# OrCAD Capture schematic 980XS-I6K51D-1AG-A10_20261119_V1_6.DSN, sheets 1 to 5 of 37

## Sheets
1 P0083_S8_MIPI: size A2
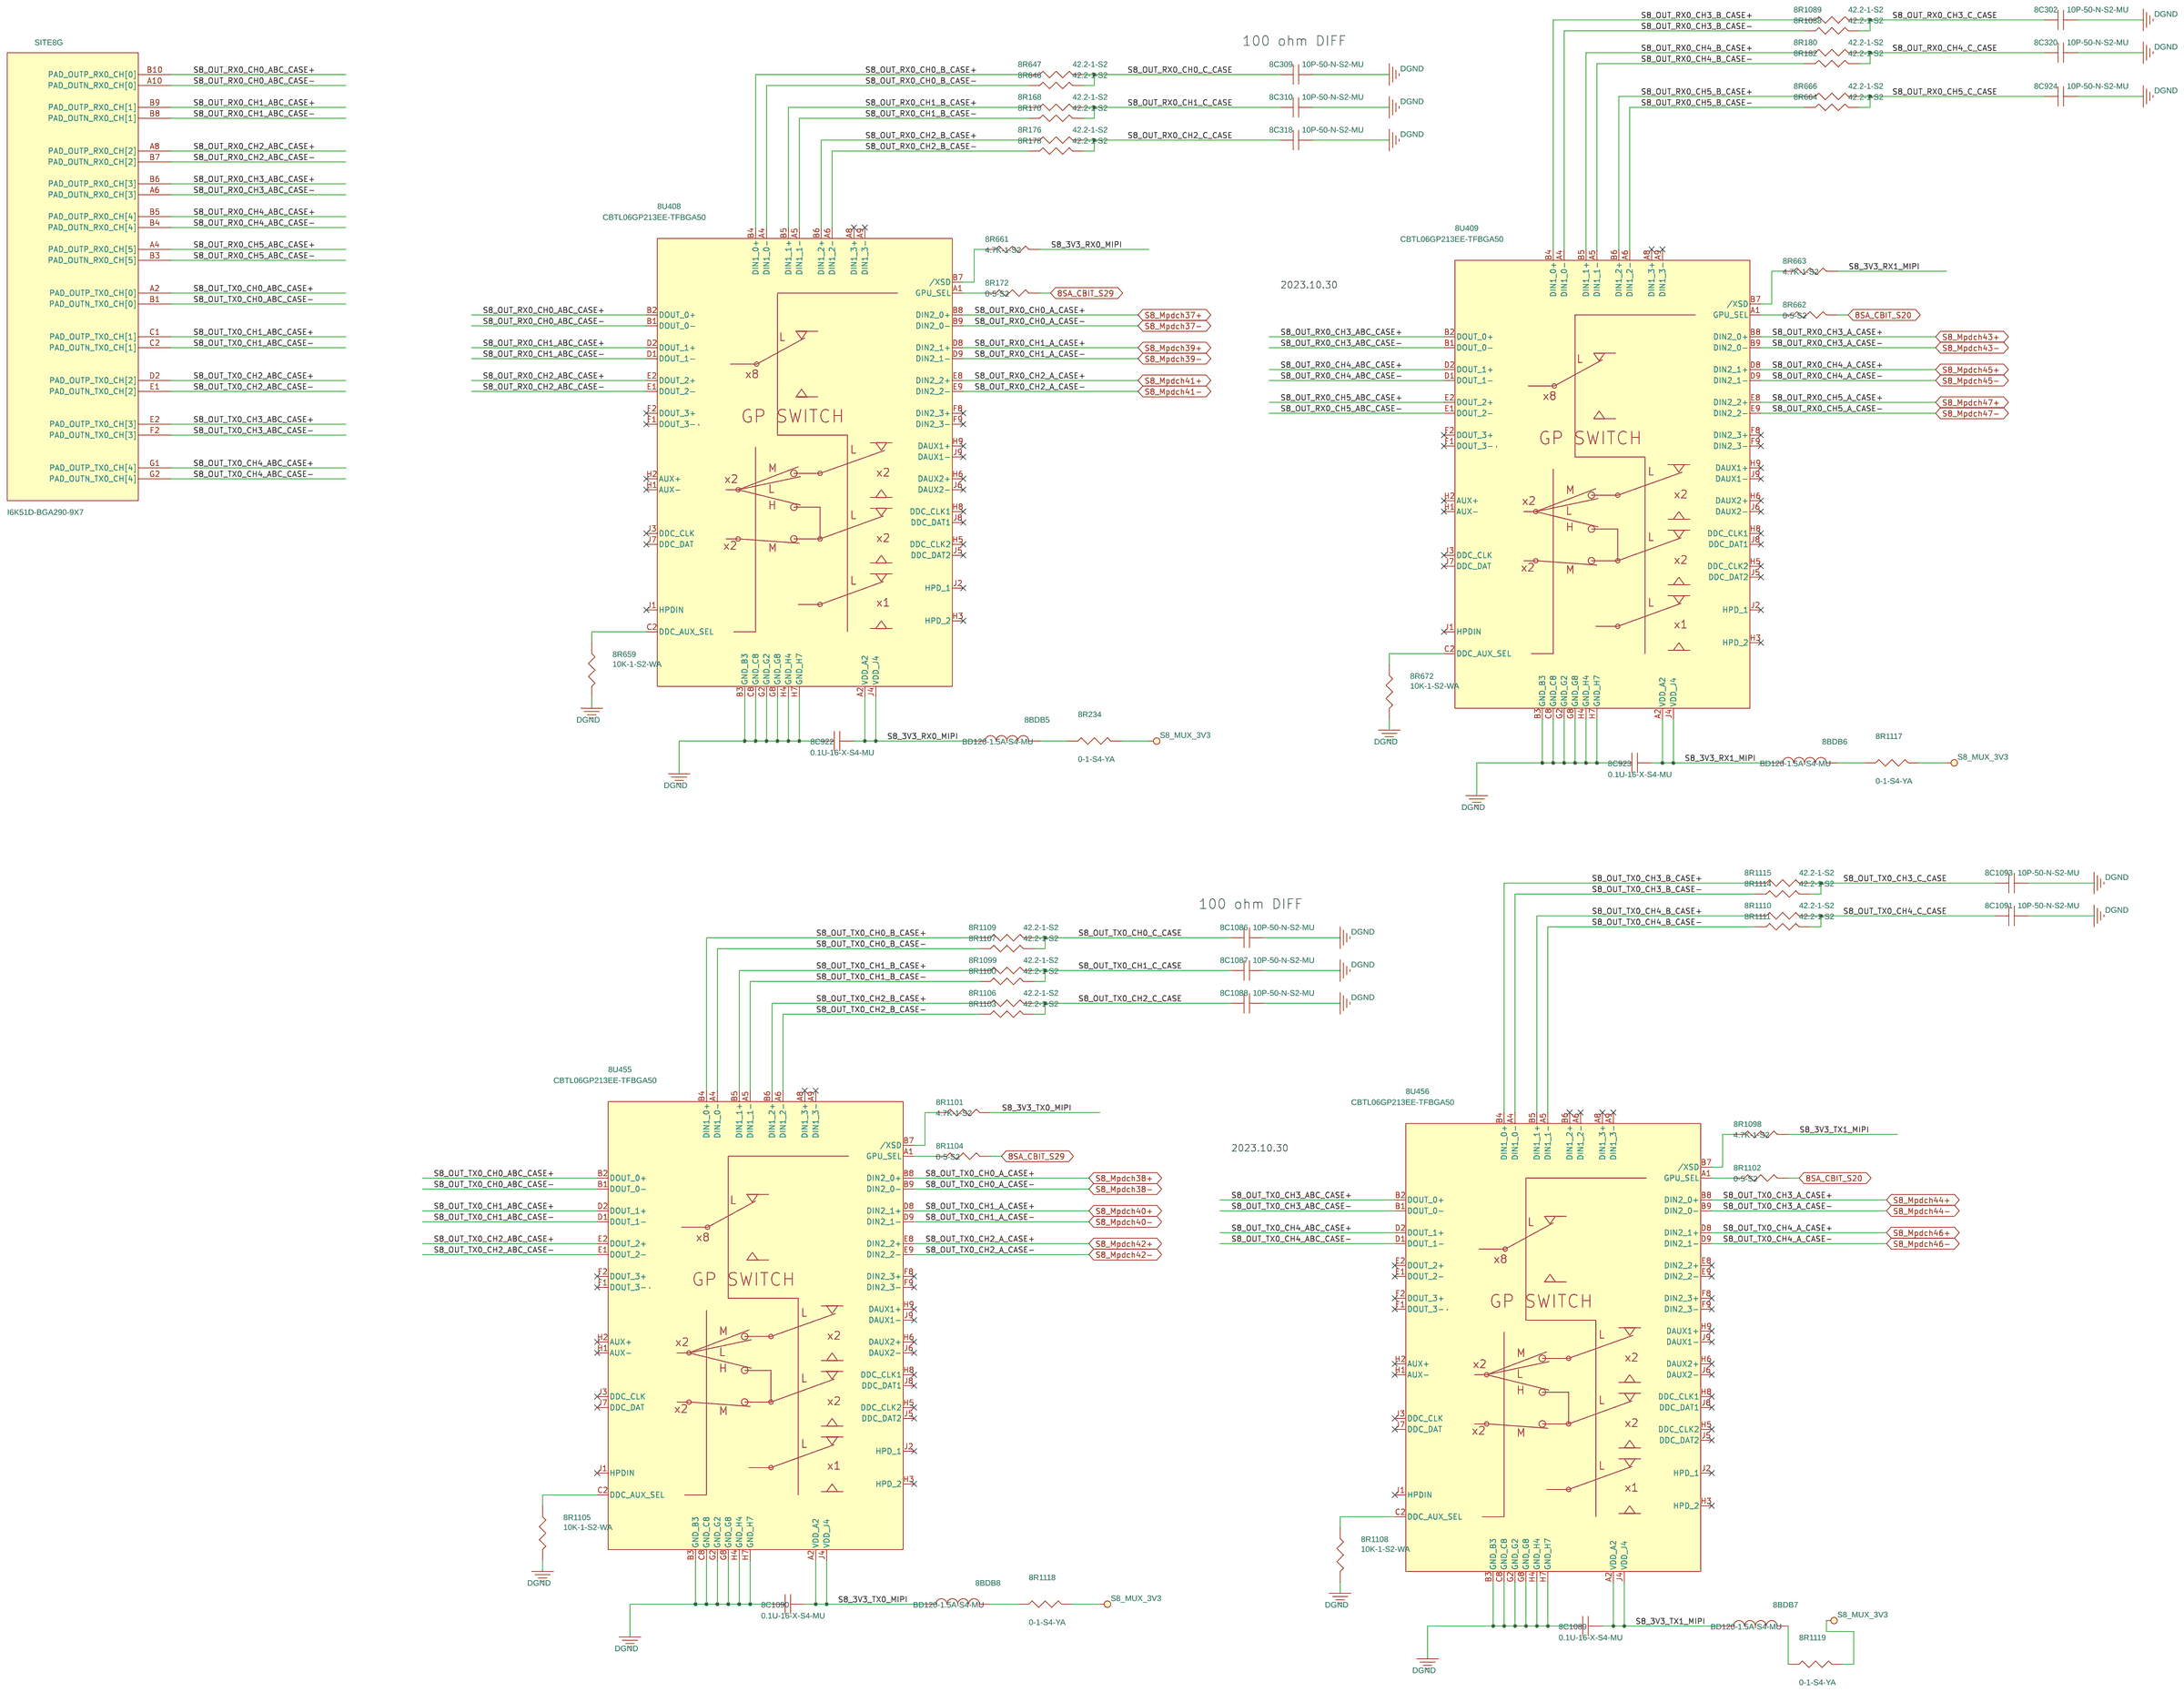
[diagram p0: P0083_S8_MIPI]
2 P0081_S8_POWER: size A2
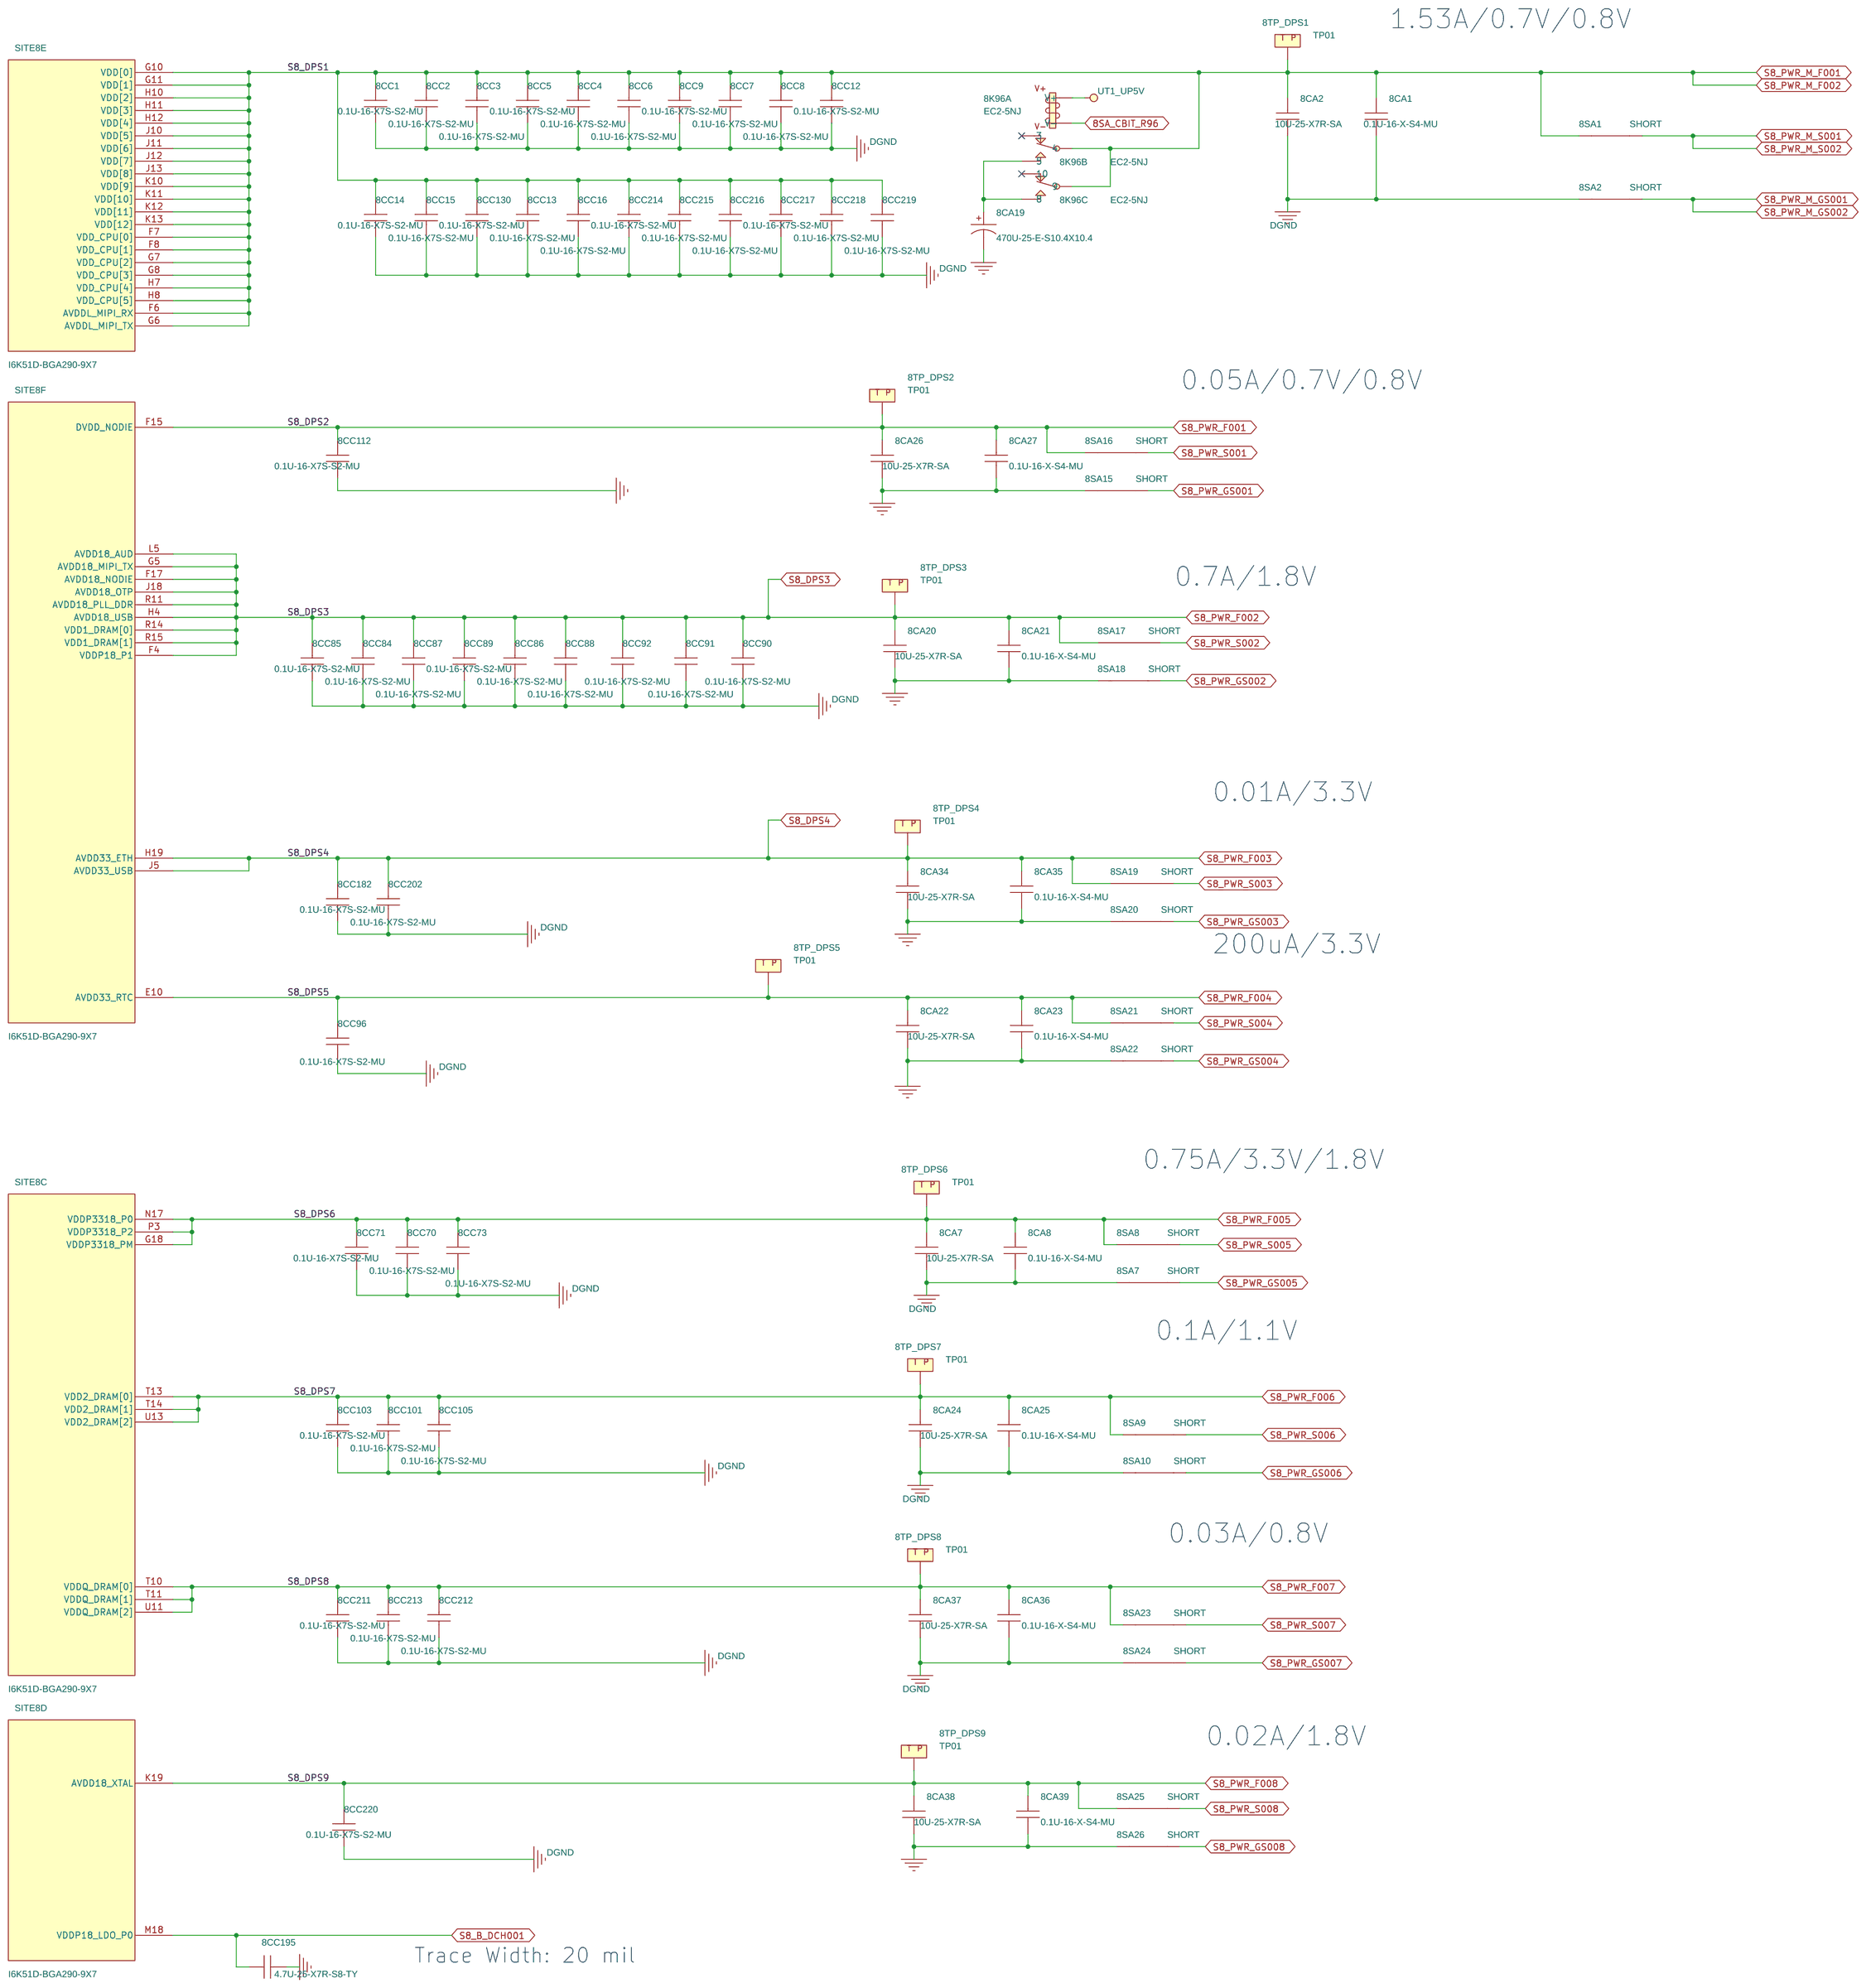
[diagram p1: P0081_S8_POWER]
3 P0073_S7_MIPI: size A2
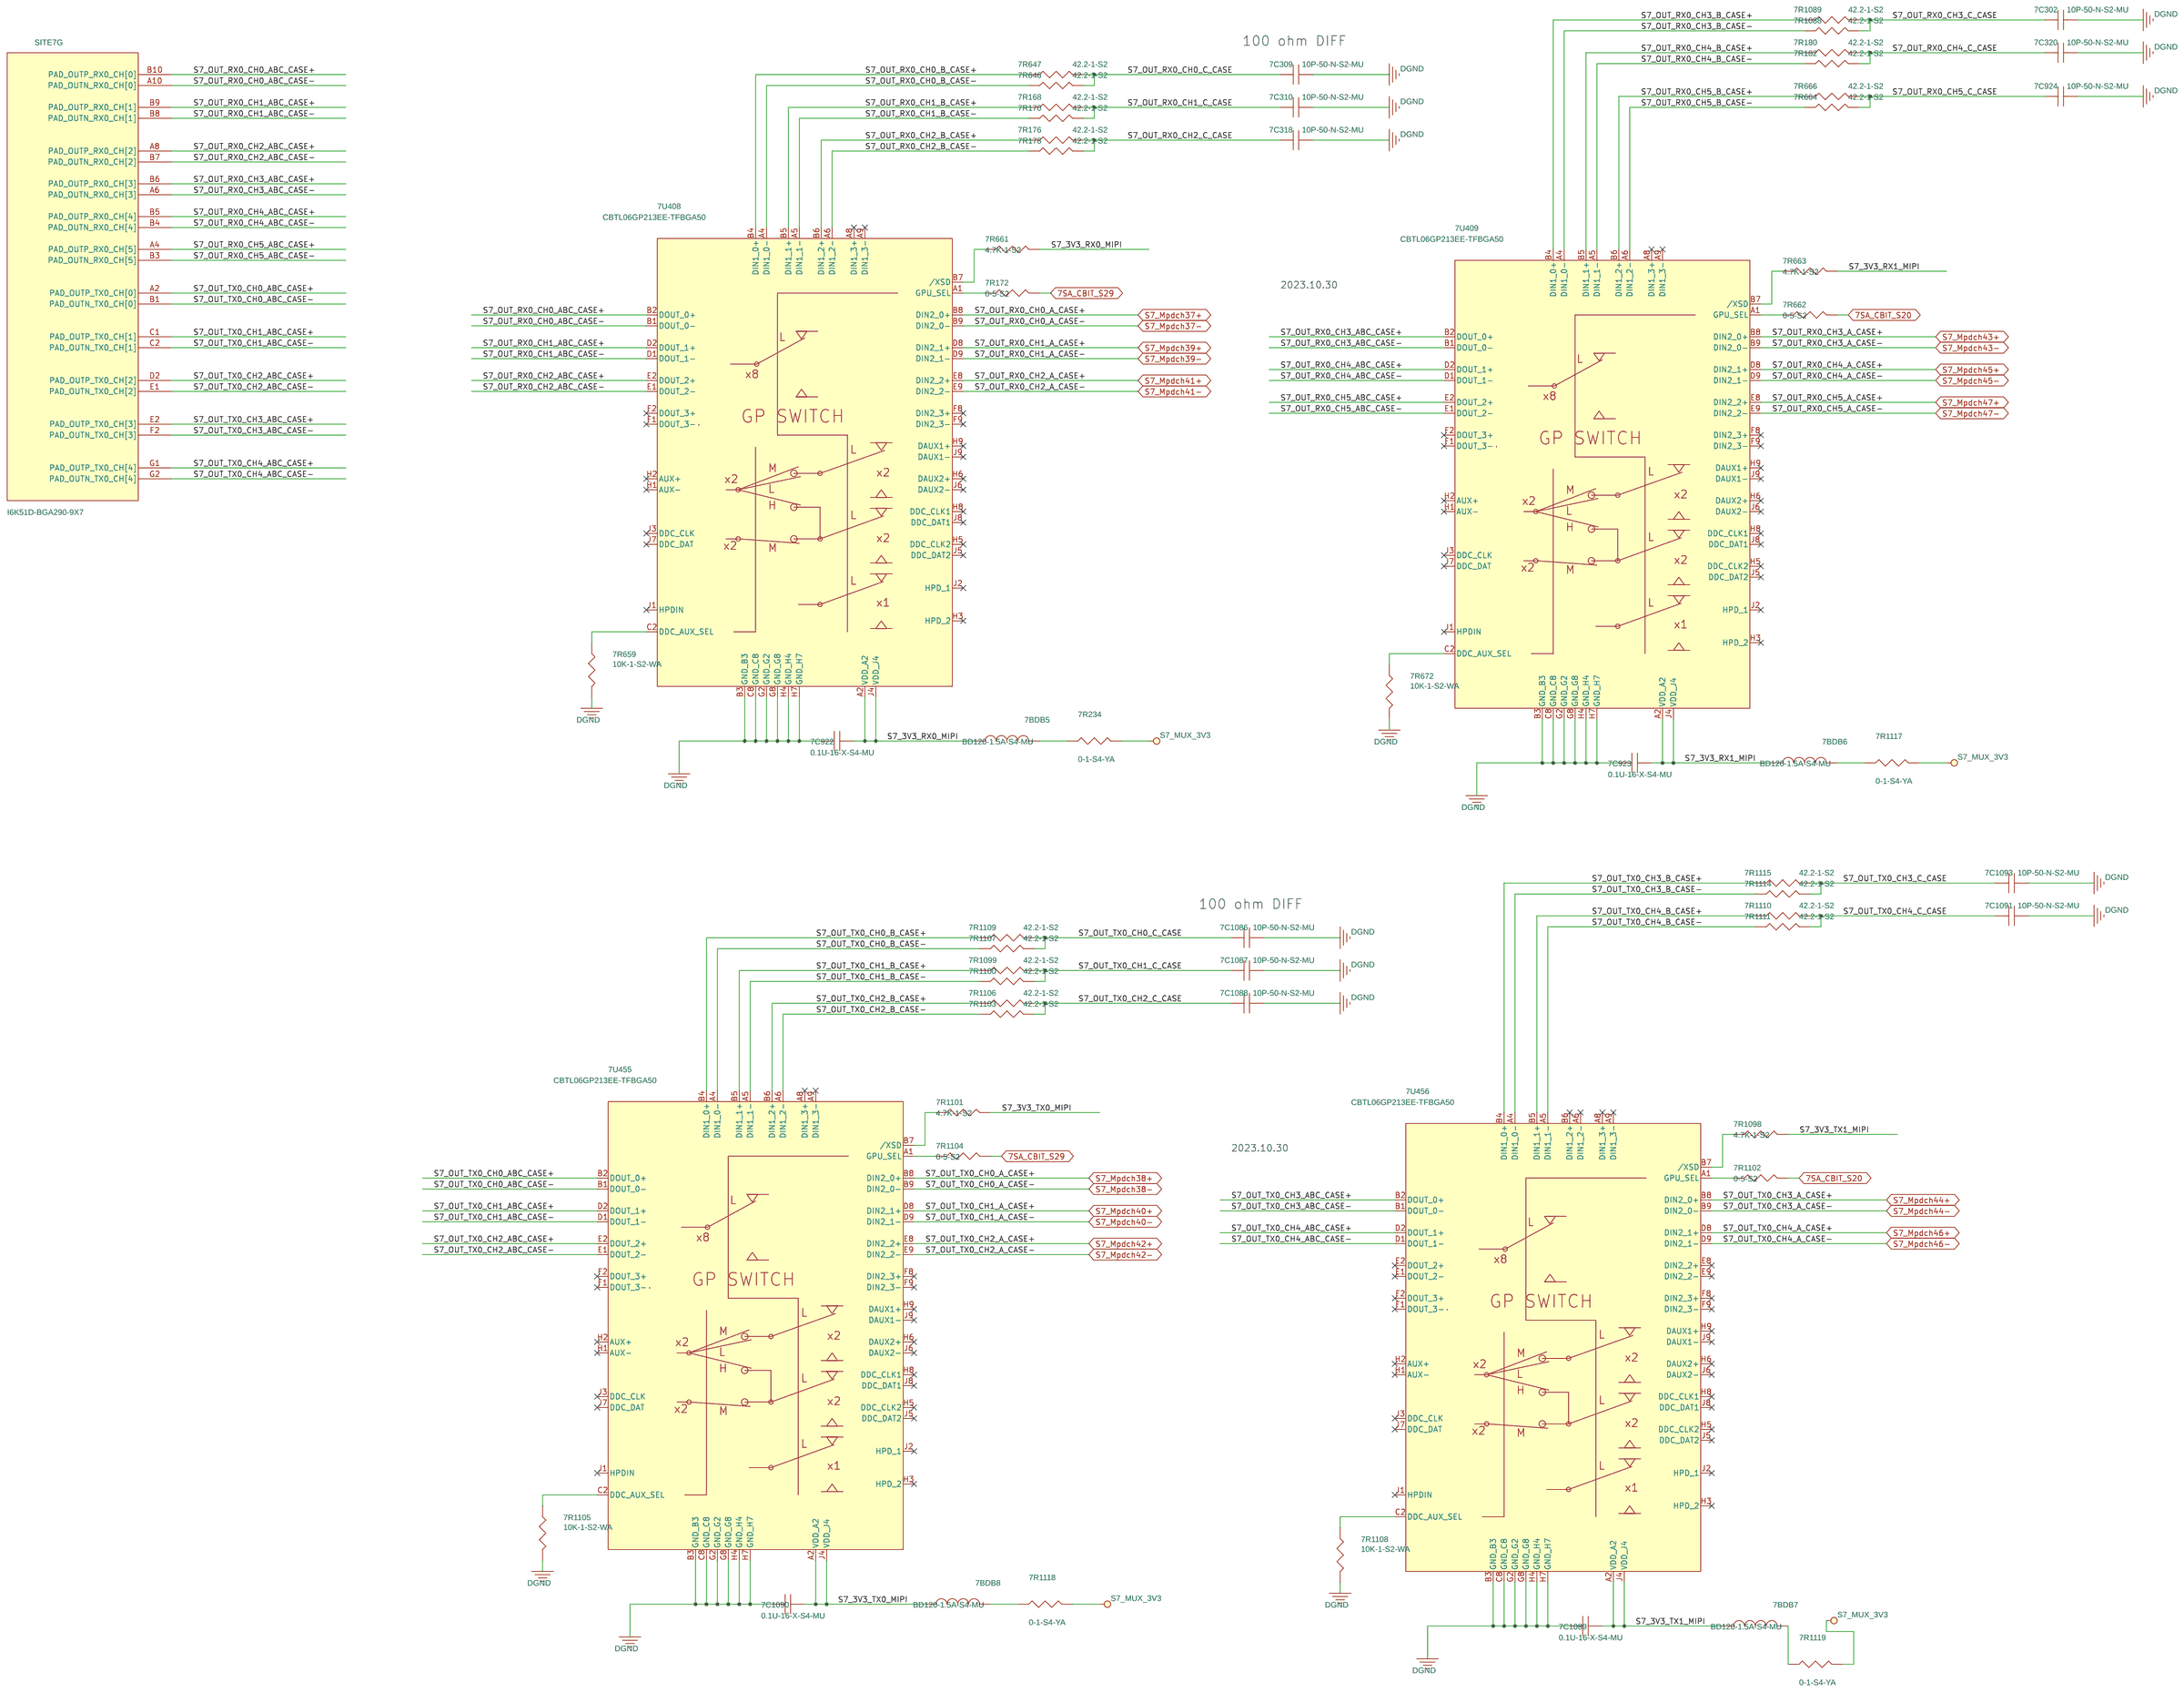
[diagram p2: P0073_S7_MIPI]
4 P0071_S7_POWER: size A2
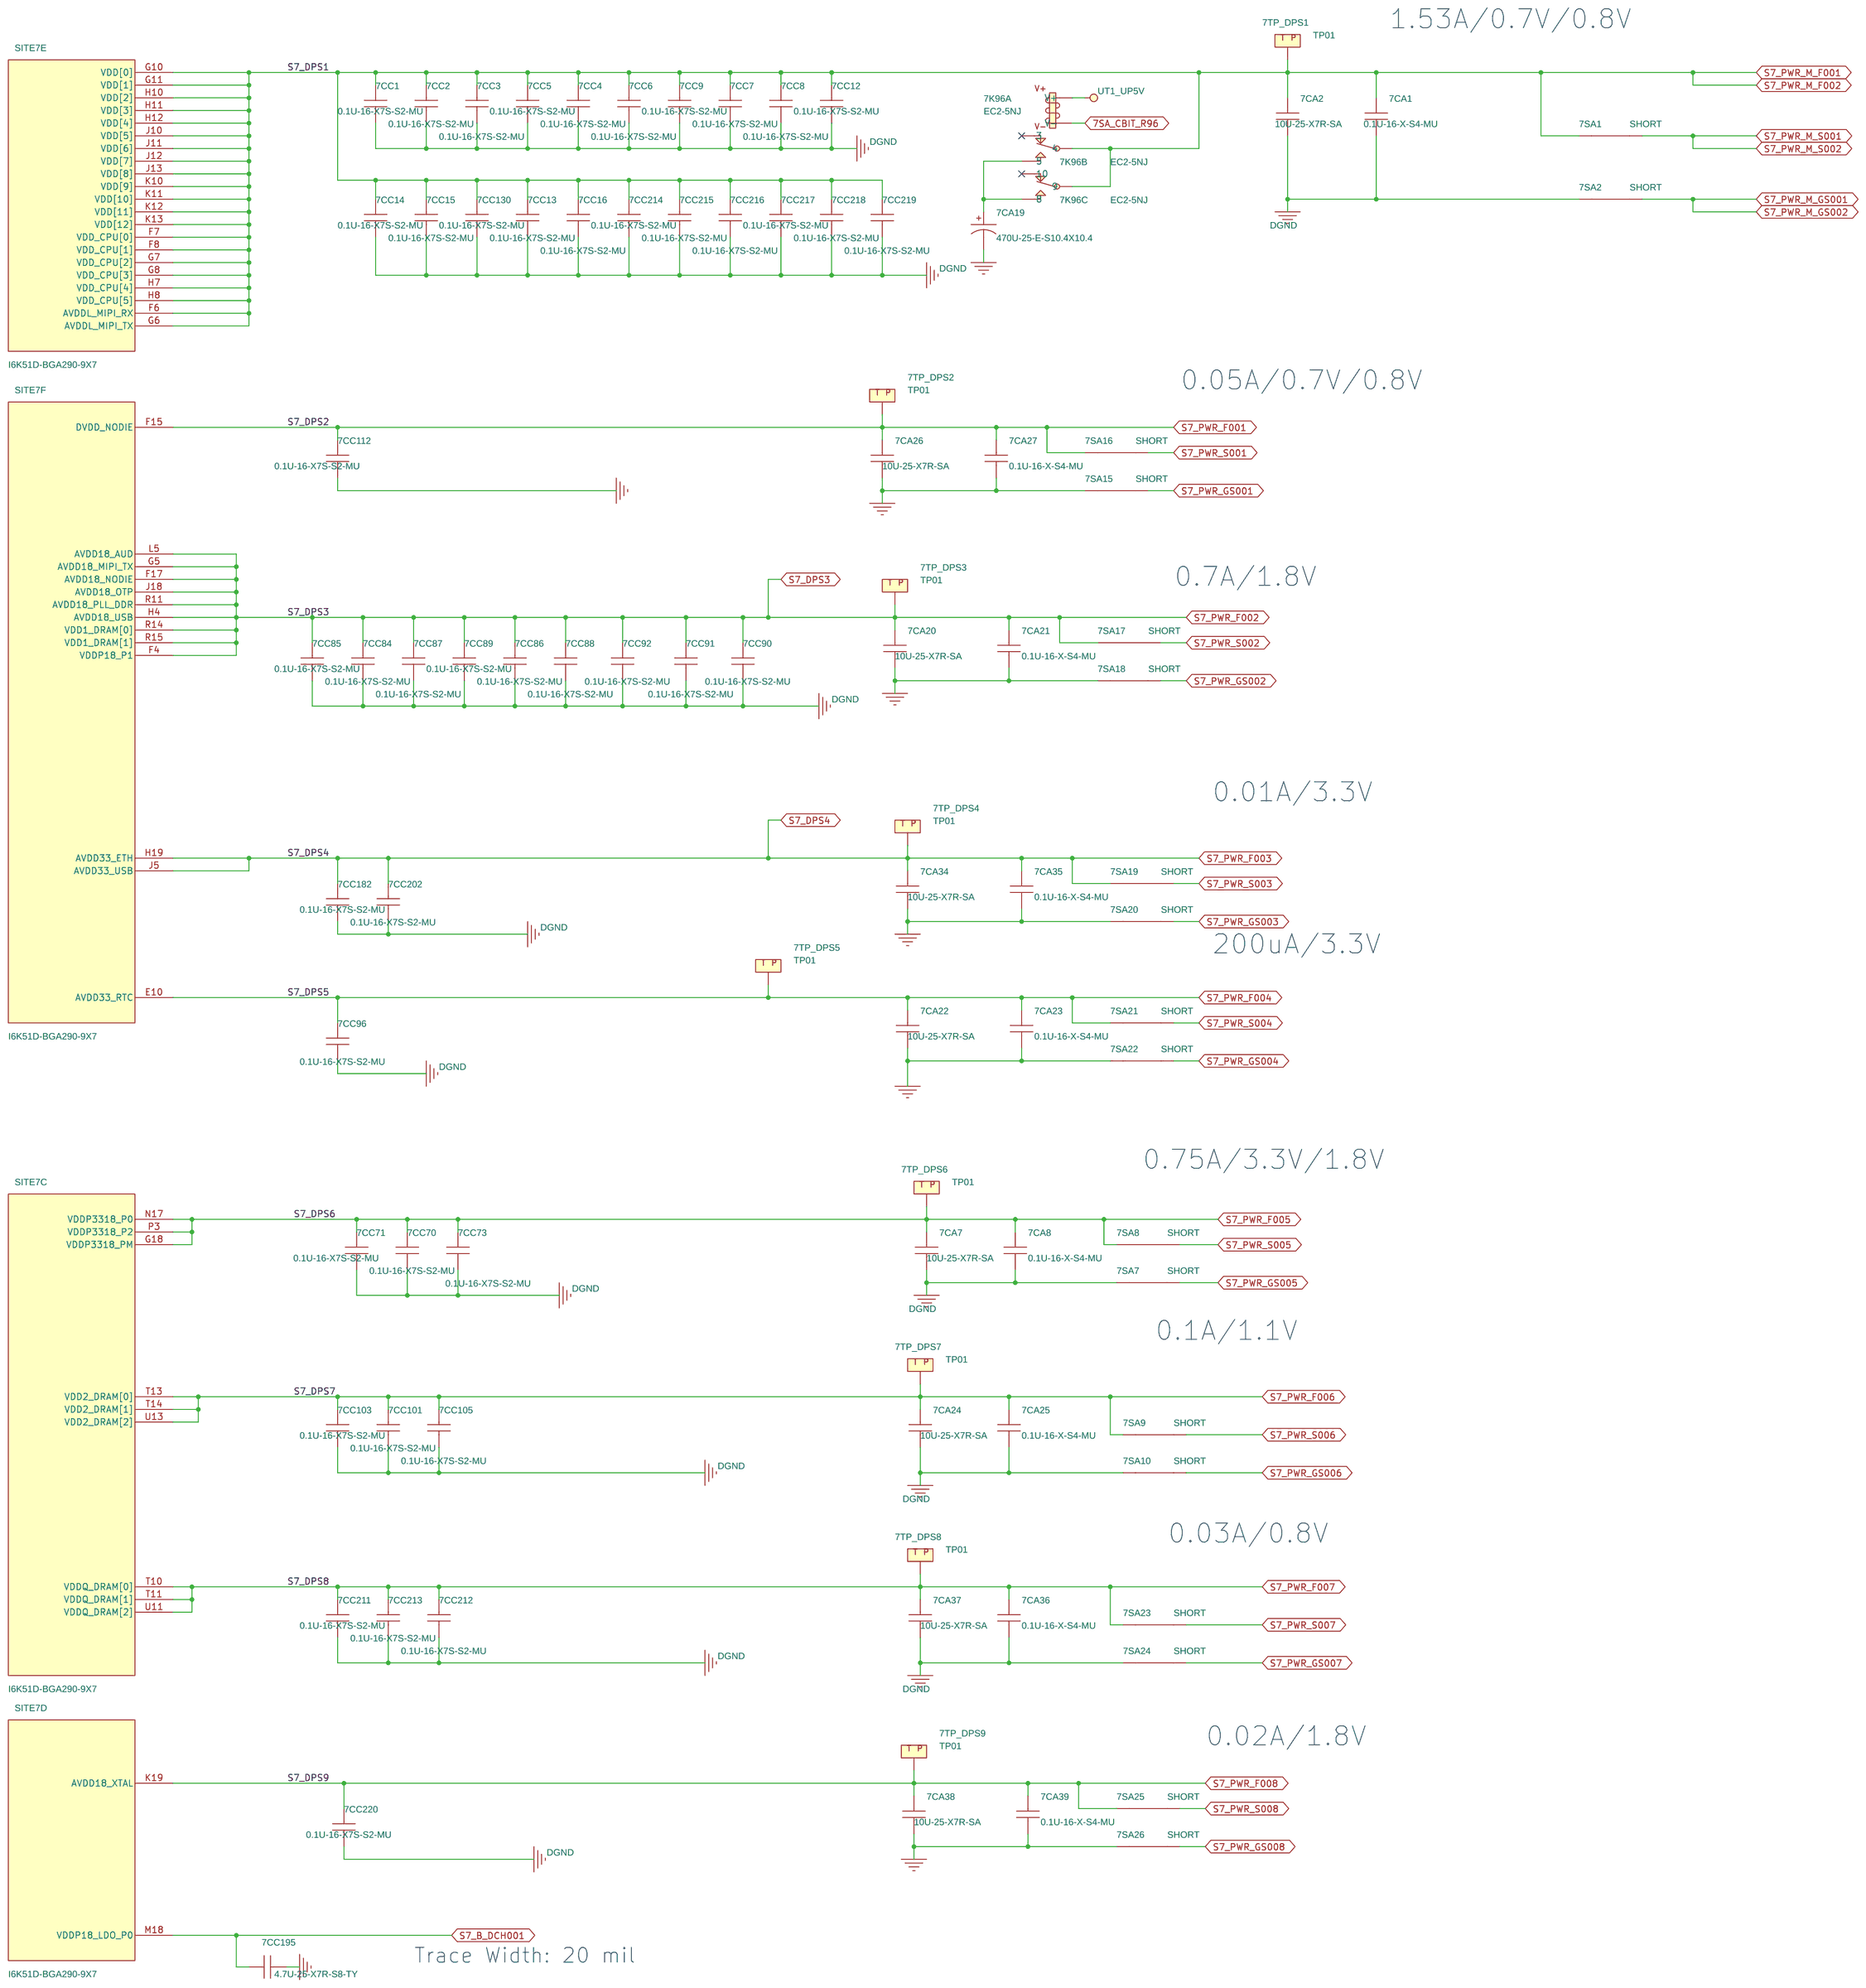
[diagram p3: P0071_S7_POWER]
5 P0063_S6_MIPI: size A2
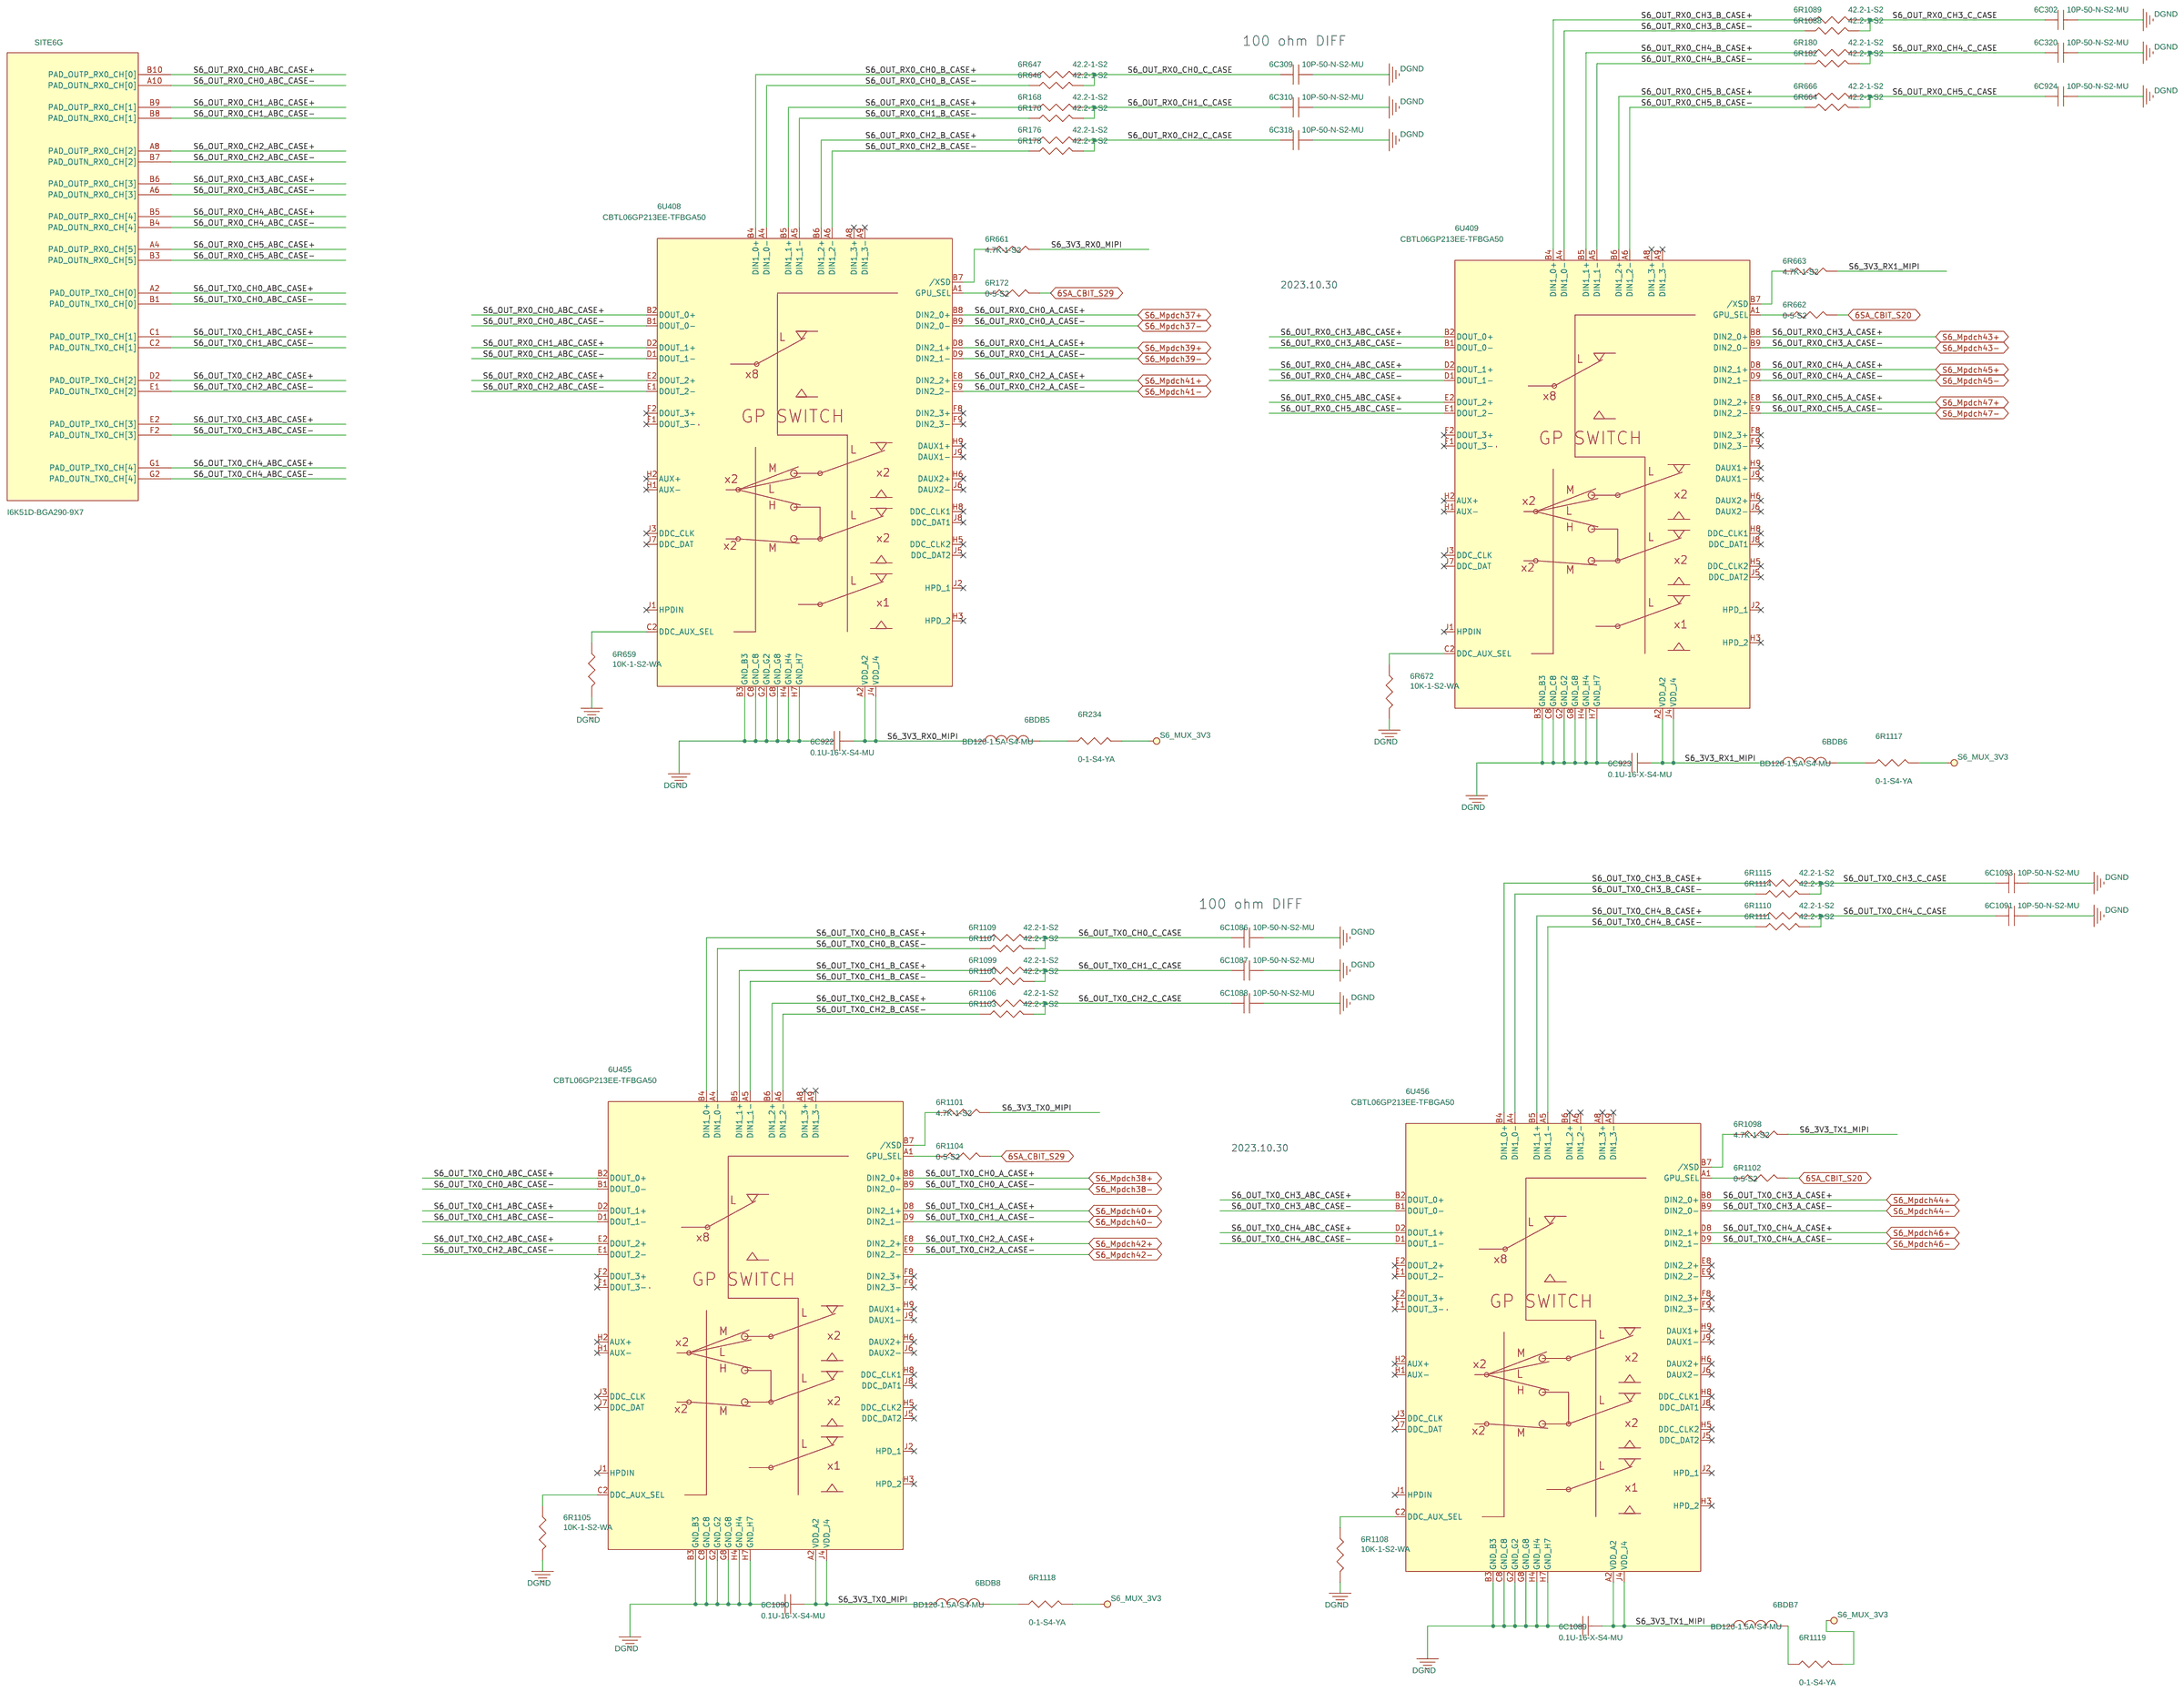
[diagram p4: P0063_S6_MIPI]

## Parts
sheet P0062_S6_USB/AUD/FLASH/XTAL
SITE6  I6K51D-BGA290-9X7  [SK_TFBGA7X9_290P_0P4MM_JG]  (sections A,B,C,D,E,F,G,H,I,J,K,L,M,N,O)
sheet P0063_S6_MIPI
6BDB5  BD120-1.5A-S4-MU  [FB0402]
6BDB6  BD120-1.5A-S4-MU  [FB0402]
6BDB7  BD120-1.5A-S4-MU  [FB0402]
6BDB8  BD120-1.5A-S4-MU  [FB0402]
6C302  10P-50-N-S2-MU  [C0201]
6C309  10P-50-N-S2-MU  [C0201]
6C310  10P-50-N-S2-MU  [C0201]
6C318  10P-50-N-S2-MU  [C0201]
6C320  10P-50-N-S2-MU  [C0201]
6C922  0.1U-16-X-S4-MU  [C0402]
6C923  0.1U-16-X-S4-MU  [C0402]
6C924  10P-50-N-S2-MU  [C0201]
6C1086  10P-50-N-S2-MU  [C0201]
6C1087  10P-50-N-S2-MU  [C0201]
6C1088  10P-50-N-S2-MU  [C0201]
6C1089  0.1U-16-X-S4-MU  [C0402]
6C1090  0.1U-16-X-S4-MU  [C0402]
6C1091  10P-50-N-S2-MU  [C0201]
6C1093  10P-50-N-S2-MU  [C0201]
6R168  42.2-1-S2  [R0201]
6R170  42.2-1-S2  [R0201]
6R172  0-5-S2  [R0201]
6R176  42.2-1-S2  [R0201]
6R178  42.2-1-S2  [R0201]
6R180  42.2-1-S2  [R0201]
6R182  42.2-1-S2  [R0201]
6R234  0-1-S4-YA  [R0402]
6R646  42.2-1-S2  [R0201]
6R647  42.2-1-S2  [R0201]
6R659  10K-1-S2-WA  [R0201]
6R661  4.7K-1-S2  [R0201]
6R662  0-5-S2  [R0201]
6R663  4.7K-1-S2  [R0201]
6R664  42.2-1-S2  [R0201]
6R666  42.2-1-S2  [R0201]
6R672  10K-1-S2-WA  [R0201]
6R1088  42.2-1-S2  [R0201]
6R1089  42.2-1-S2  [R0201]
6R1098  4.7K-1-S2  [R0201]
6R1099  42.2-1-S2  [R0201]
6R1100  42.2-1-S2  [R0201]
6R1101  4.7K-1-S2  [R0201]
6R1102  0-5-S2  [R0201]
6R1103  42.2-1-S2  [R0201]
6R1104  0-5-S2  [R0201]
6R1105  10K-1-S2-WA  [R0201]
6R1106  42.2-1-S2  [R0201]
6R1107  42.2-1-S2  [R0201]
6R1108  10K-1-S2-WA  [R0201]
6R1109  42.2-1-S2  [R0201]
6R1110  42.2-1-S2  [R0201]
6R1111  42.2-1-S2  [R0201]
6R1114  42.2-1-S2  [R0201]
6R1115  42.2-1-S2  [R0201]
6R1117  0-1-S4-YA  [R0402]
6R1118  0-1-S4-YA  [R0402]
6R1119  0-1-S4-YA  [R0402]
6U408  CBTL06GP213EE-TFBGA50  [TFBGA9X9_50P_0P5MM]
6U409  CBTL06GP213EE-TFBGA50  [TFBGA9X9_50P_0P5MM]
6U455  CBTL06GP213EE-TFBGA50  [TFBGA9X9_50P_0P5MM]
6U456  CBTL06GP213EE-TFBGA50  [TFBGA9X9_50P_0P5MM]
sheet P0071_S7_POWER
7CA1  0.1U-16-X-S4-MU  [C0402]
7CA2  10U-25-X7R-SA  [C1206]
7CA7  10U-25-X7R-SA  [C1206]
7CA8  0.1U-16-X-S4-MU  [C0402]
7CA19  470U-25-E-S10.4X10.4  [EC_10P3X10_S]
7CA20  10U-25-X7R-SA  [C1206]
7CA21  0.1U-16-X-S4-MU  [C0402]
7CA22  10U-25-X7R-SA  [C1206]
7CA23  0.1U-16-X-S4-MU  [C0402]
7CA24  10U-25-X7R-SA  [C1206]
7CA25  0.1U-16-X-S4-MU  [C0402]
7CA26  10U-25-X7R-SA  [C1206]
7CA27  0.1U-16-X-S4-MU  [C0402]
7CA34  10U-25-X7R-SA  [C1206]
7CA35  0.1U-16-X-S4-MU  [C0402]
7CA36  0.1U-16-X-S4-MU  [C0402]
7CA37  10U-25-X7R-SA  [C1206]
7CA38  10U-25-X7R-SA  [C1206]
7CA39  0.1U-16-X-S4-MU  [C0402]
7CC1  0.1U-16-X7S-S2-MU  [C0201_MINI]
7CC2  0.1U-16-X7S-S2-MU  [C0201_MINI]
7CC3  0.1U-16-X7S-S2-MU  [C0201_MINI]
7CC4  0.1U-16-X7S-S2-MU  [C0201_MINI]
7CC5  0.1U-16-X7S-S2-MU  [C0201_MINI]
7CC6  0.1U-16-X7S-S2-MU  [C0201_MINI]
7CC7  0.1U-16-X7S-S2-MU  [C0201_MINI]
7CC8  0.1U-16-X7S-S2-MU  [C0201_MINI]
7CC9  0.1U-16-X7S-S2-MU  [C0201_MINI]
7CC12  0.1U-16-X7S-S2-MU  [C0201_MINI]
7CC13  0.1U-16-X7S-S2-MU  [C0201_MINI]
7CC14  0.1U-16-X7S-S2-MU  [C0201_MINI]
7CC15  0.1U-16-X7S-S2-MU  [C0201_MINI]
7CC16  0.1U-16-X7S-S2-MU  [C0201_MINI]
7CC70  0.1U-16-X7S-S2-MU  [C0201_MINI]
7CC71  0.1U-16-X7S-S2-MU  [C0201_MINI]
7CC73  0.1U-16-X7S-S2-MU  [C0201_MINI]
7CC84  0.1U-16-X7S-S2-MU  [C0201_MINI]
7CC85  0.1U-16-X7S-S2-MU  [C0201_MINI]
7CC86  0.1U-16-X7S-S2-MU  [C0201_MINI]
7CC87  0.1U-16-X7S-S2-MU  [C0201_MINI]
7CC88  0.1U-16-X7S-S2-MU  [C0201_MINI]
7CC89  0.1U-16-X7S-S2-MU  [C0201_MINI]
7CC90  0.1U-16-X7S-S2-MU  [C0201_MINI]
7CC91  0.1U-16-X7S-S2-MU  [C0201_MINI]
7CC92  0.1U-16-X7S-S2-MU  [C0201_MINI]
7CC96  0.1U-16-X7S-S2-MU  [C0201_MINI]
7CC101  0.1U-16-X7S-S2-MU  [C0201_MINI]
7CC103  0.1U-16-X7S-S2-MU  [C0201_MINI]
7CC105  0.1U-16-X7S-S2-MU  [C0201_MINI]
7CC112  0.1U-16-X7S-S2-MU  [C0201_MINI]
7CC130  0.1U-16-X7S-S2-MU  [C0201_MINI]
7CC182  0.1U-16-X7S-S2-MU  [C0201_MINI]
7CC195  4.7U-25-X7R-S8-TY  [C0805]
7CC202  0.1U-16-X7S-S2-MU  [C0201_MINI]
7CC211  0.1U-16-X7S-S2-MU  [C0201_MINI]
7CC212  0.1U-16-X7S-S2-MU  [C0201_MINI]
7CC213  0.1U-16-X7S-S2-MU  [C0201_MINI]
7CC214  0.1U-16-X7S-S2-MU  [C0201_MINI]
7CC215  0.1U-16-X7S-S2-MU  [C0201_MINI]
7CC216  0.1U-16-X7S-S2-MU  [C0201_MINI]
7CC217  0.1U-16-X7S-S2-MU  [C0201_MINI]
7CC218  0.1U-16-X7S-S2-MU  [C0201_MINI]
7CC219  0.1U-16-X7S-S2-MU  [C0201_MINI]
7CC220  0.1U-16-X7S-S2-MU  [C0201_MINI]
7K96  EC2-5NJ  [RL_NECEC2_10P_5V]  (sections A,B,C)
7SA1  SHORT  [DEFAULT_SHORT_SMALL]
7SA2  SHORT  [DEFAULT_SHORT_SMALL]
7SA7  SHORT  [DEFAULT_SHORT_SMALL]
7SA8  SHORT  [DEFAULT_SHORT_SMALL]
7SA9  SHORT  [DEFAULT_SHORT_SMALL]
7SA10  SHORT  [DEFAULT_SHORT_SMALL]
7SA15  SHORT  [DEFAULT_SHORT_SMALL]
7SA16  SHORT  [DEFAULT_SHORT_SMALL]
7SA17  SHORT  [DEFAULT_SHORT_SMALL]
7SA18  SHORT  [DEFAULT_SHORT_SMALL]
7SA19  SHORT  [DEFAULT_SHORT_SMALL]
7SA20  SHORT  [DEFAULT_SHORT_SMALL]
7SA21  SHORT  [DEFAULT_SHORT_SMALL]
7SA22  SHORT  [DEFAULT_SHORT_SMALL]
7SA23  SHORT  [DEFAULT_SHORT_SMALL]
7SA24  SHORT  [DEFAULT_SHORT_SMALL]
7SA25  SHORT  [DEFAULT_SHORT_SMALL]
7SA26  SHORT  [DEFAULT_SHORT_SMALL]
7TP_DPS1  TP01  [TP_040_T]
7TP_DPS2  TP01  [TP_040_T]
7TP_DPS3  TP01  [TP_040_T]
7TP_DPS4  TP01  [TP_040_T]
7TP_DPS5  TP01  [TP_040_T]
7TP_DPS6  TP01  [TP_040_T]
7TP_DPS7  TP01  [TP_040_T]
7TP_DPS8  TP01  [TP_040_T]
7TP_DPS9  TP01  [TP_040_T]
sheet P0072_S7_USB/AUD/FLASH/XTAL
SITE7  I6K51D-BGA290-9X7  [SK_TFBGA7X9_290P_0P4MM_JG]  (sections A,B,C,D,E,F,G,H,I,J,K,L,M,N,O)
sheet P0073_S7_MIPI
7BDB5  BD120-1.5A-S4-MU  [FB0402]
7BDB6  BD120-1.5A-S4-MU  [FB0402]
7BDB7  BD120-1.5A-S4-MU  [FB0402]
7BDB8  BD120-1.5A-S4-MU  [FB0402]
7C302  10P-50-N-S2-MU  [C0201]
7C309  10P-50-N-S2-MU  [C0201]
7C310  10P-50-N-S2-MU  [C0201]
7C318  10P-50-N-S2-MU  [C0201]
7C320  10P-50-N-S2-MU  [C0201]
7C922  0.1U-16-X-S4-MU  [C0402]
7C923  0.1U-16-X-S4-MU  [C0402]
7C924  10P-50-N-S2-MU  [C0201]
7C1086  10P-50-N-S2-MU  [C0201]
7C1087  10P-50-N-S2-MU  [C0201]
7C1088  10P-50-N-S2-MU  [C0201]
7C1089  0.1U-16-X-S4-MU  [C0402]
7C1090  0.1U-16-X-S4-MU  [C0402]
7C1091  10P-50-N-S2-MU  [C0201]
7C1093  10P-50-N-S2-MU  [C0201]
7R168  42.2-1-S2  [R0201]
7R170  42.2-1-S2  [R0201]
7R172  0-5-S2  [R0201]
7R176  42.2-1-S2  [R0201]
7R178  42.2-1-S2  [R0201]
7R180  42.2-1-S2  [R0201]
7R182  42.2-1-S2  [R0201]
7R234  0-1-S4-YA  [R0402]
7R646  42.2-1-S2  [R0201]
7R647  42.2-1-S2  [R0201]
7R659  10K-1-S2-WA  [R0201]
7R661  4.7K-1-S2  [R0201]
7R662  0-5-S2  [R0201]
7R663  4.7K-1-S2  [R0201]
7R664  42.2-1-S2  [R0201]
7R666  42.2-1-S2  [R0201]
7R672  10K-1-S2-WA  [R0201]
7R1088  42.2-1-S2  [R0201]
7R1089  42.2-1-S2  [R0201]
7R1098  4.7K-1-S2  [R0201]
7R1099  42.2-1-S2  [R0201]
7R1100  42.2-1-S2  [R0201]
7R1101  4.7K-1-S2  [R0201]
7R1102  0-5-S2  [R0201]
7R1103  42.2-1-S2  [R0201]
7R1104  0-5-S2  [R0201]
7R1105  10K-1-S2-WA  [R0201]
7R1106  42.2-1-S2  [R0201]
7R1107  42.2-1-S2  [R0201]
7R1108  10K-1-S2-WA  [R0201]
7R1109  42.2-1-S2  [R0201]
7R1110  42.2-1-S2  [R0201]
7R1111  42.2-1-S2  [R0201]
7R1114  42.2-1-S2  [R0201]
7R1115  42.2-1-S2  [R0201]
7R1117  0-1-S4-YA  [R0402]
7R1118  0-1-S4-YA  [R0402]
7R1119  0-1-S4-YA  [R0402]
7U408  CBTL06GP213EE-TFBGA50  [TFBGA9X9_50P_0P5MM]
7U409  CBTL06GP213EE-TFBGA50  [TFBGA9X9_50P_0P5MM]
7U455  CBTL06GP213EE-TFBGA50  [TFBGA9X9_50P_0P5MM]
7U456  CBTL06GP213EE-TFBGA50  [TFBGA9X9_50P_0P5MM]
sheet P0081_S8_POWER
8CA1  0.1U-16-X-S4-MU  [C0402]
8CA2  10U-25-X7R-SA  [C1206]
8CA7  10U-25-X7R-SA  [C1206]
8CA8  0.1U-16-X-S4-MU  [C0402]
8CA19  470U-25-E-S10.4X10.4  [EC_10P3X10_S]
8CA20  10U-25-X7R-SA  [C1206]
8CA21  0.1U-16-X-S4-MU  [C0402]
8CA22  10U-25-X7R-SA  [C1206]
8CA23  0.1U-16-X-S4-MU  [C0402]
8CA24  10U-25-X7R-SA  [C1206]
8CA25  0.1U-16-X-S4-MU  [C0402]
8CA26  10U-25-X7R-SA  [C1206]
8CA27  0.1U-16-X-S4-MU  [C0402]
8CA34  10U-25-X7R-SA  [C1206]
8CA35  0.1U-16-X-S4-MU  [C0402]
8CA36  0.1U-16-X-S4-MU  [C0402]
8CA37  10U-25-X7R-SA  [C1206]
8CA38  10U-25-X7R-SA  [C1206]
8CA39  0.1U-16-X-S4-MU  [C0402]
8CC1  0.1U-16-X7S-S2-MU  [C0201_MINI]
8CC2  0.1U-16-X7S-S2-MU  [C0201_MINI]
8CC3  0.1U-16-X7S-S2-MU  [C0201_MINI]
8CC4  0.1U-16-X7S-S2-MU  [C0201_MINI]
8CC5  0.1U-16-X7S-S2-MU  [C0201_MINI]
8CC6  0.1U-16-X7S-S2-MU  [C0201_MINI]
8CC7  0.1U-16-X7S-S2-MU  [C0201_MINI]
8CC8  0.1U-16-X7S-S2-MU  [C0201_MINI]
8CC9  0.1U-16-X7S-S2-MU  [C0201_MINI]
8CC12  0.1U-16-X7S-S2-MU  [C0201_MINI]
8CC13  0.1U-16-X7S-S2-MU  [C0201_MINI]
8CC14  0.1U-16-X7S-S2-MU  [C0201_MINI]
8CC15  0.1U-16-X7S-S2-MU  [C0201_MINI]
8CC16  0.1U-16-X7S-S2-MU  [C0201_MINI]
8CC70  0.1U-16-X7S-S2-MU  [C0201_MINI]
8CC71  0.1U-16-X7S-S2-MU  [C0201_MINI]
8CC73  0.1U-16-X7S-S2-MU  [C0201_MINI]
8CC84  0.1U-16-X7S-S2-MU  [C0201_MINI]
8CC85  0.1U-16-X7S-S2-MU  [C0201_MINI]
8CC86  0.1U-16-X7S-S2-MU  [C0201_MINI]
8CC87  0.1U-16-X7S-S2-MU  [C0201_MINI]
8CC88  0.1U-16-X7S-S2-MU  [C0201_MINI]
8CC89  0.1U-16-X7S-S2-MU  [C0201_MINI]
8CC90  0.1U-16-X7S-S2-MU  [C0201_MINI]
8CC91  0.1U-16-X7S-S2-MU  [C0201_MINI]
8CC92  0.1U-16-X7S-S2-MU  [C0201_MINI]
8CC96  0.1U-16-X7S-S2-MU  [C0201_MINI]
8CC101  0.1U-16-X7S-S2-MU  [C0201_MINI]
8CC103  0.1U-16-X7S-S2-MU  [C0201_MINI]
8CC105  0.1U-16-X7S-S2-MU  [C0201_MINI]
8CC112  0.1U-16-X7S-S2-MU  [C0201_MINI]
8CC130  0.1U-16-X7S-S2-MU  [C0201_MINI]
8CC182  0.1U-16-X7S-S2-MU  [C0201_MINI]
8CC195  4.7U-25-X7R-S8-TY  [C0805]
8CC202  0.1U-16-X7S-S2-MU  [C0201_MINI]
8CC211  0.1U-16-X7S-S2-MU  [C0201_MINI]
8CC212  0.1U-16-X7S-S2-MU  [C0201_MINI]
8CC213  0.1U-16-X7S-S2-MU  [C0201_MINI]
8CC214  0.1U-16-X7S-S2-MU  [C0201_MINI]
8CC215  0.1U-16-X7S-S2-MU  [C0201_MINI]
8CC216  0.1U-16-X7S-S2-MU  [C0201_MINI]
8CC217  0.1U-16-X7S-S2-MU  [C0201_MINI]
8CC218  0.1U-16-X7S-S2-MU  [C0201_MINI]
8CC219  0.1U-16-X7S-S2-MU  [C0201_MINI]
8CC220  0.1U-16-X7S-S2-MU  [C0201_MINI]
8K96  EC2-5NJ  [RL_NECEC2_10P_5V]  (sections A,B,C)
8SA1  SHORT  [DEFAULT_SHORT_SMALL]
8SA2  SHORT  [DEFAULT_SHORT_SMALL]
8SA7  SHORT  [DEFAULT_SHORT_SMALL]
8SA8  SHORT  [DEFAULT_SHORT_SMALL]
8SA9  SHORT  [DEFAULT_SHORT_SMALL]
8SA10  SHORT  [DEFAULT_SHORT_SMALL]
8SA15  SHORT  [DEFAULT_SHORT_SMALL]
8SA16  SHORT  [DEFAULT_SHORT_SMALL]
8SA17  SHORT  [DEFAULT_SHORT_SMALL]
8SA18  SHORT  [DEFAULT_SHORT_SMALL]
8SA19  SHORT  [DEFAULT_SHORT_SMALL]
8SA20  SHORT  [DEFAULT_SHORT_SMALL]
8SA21  SHORT  [DEFAULT_SHORT_SMALL]
8SA22  SHORT  [DEFAULT_SHORT_SMALL]
8SA23  SHORT  [DEFAULT_SHORT_SMALL]
8SA24  SHORT  [DEFAULT_SHORT_SMALL]
8SA25  SHORT  [DEFAULT_SHORT_SMALL]
8SA26  SHORT  [DEFAULT_SHORT_SMALL]
8TP_DPS1  TP01  [TP_040_T]
8TP_DPS2  TP01  [TP_040_T]
8TP_DPS3  TP01  [TP_040_T]
8TP_DPS4  TP01  [TP_040_T]
8TP_DPS5  TP01  [TP_040_T]
8TP_DPS6  TP01  [TP_040_T]
8TP_DPS7  TP01  [TP_040_T]
8TP_DPS8  TP01  [TP_040_T]
8TP_DPS9  TP01  [TP_040_T]
sheet P0083_S8_MIPI
8BDB5  BD120-1.5A-S4-MU  [FB0402]
8BDB6  BD120-1.5A-S4-MU  [FB0402]
8BDB7  BD120-1.5A-S4-MU  [FB0402]
8BDB8  BD120-1.5A-S4-MU  [FB0402]
8C302  10P-50-N-S2-MU  [C0201]
8C309  10P-50-N-S2-MU  [C0201]
8C310  10P-50-N-S2-MU  [C0201]
8C318  10P-50-N-S2-MU  [C0201]
8C320  10P-50-N-S2-MU  [C0201]
8C922  0.1U-16-X-S4-MU  [C0402]
8C923  0.1U-16-X-S4-MU  [C0402]
8C924  10P-50-N-S2-MU  [C0201]
8C1086  10P-50-N-S2-MU  [C0201]
8C1087  10P-50-N-S2-MU  [C0201]
8C1088  10P-50-N-S2-MU  [C0201]
8C1089  0.1U-16-X-S4-MU  [C0402]
8C1090  0.1U-16-X-S4-MU  [C0402]
8C1091  10P-50-N-S2-MU  [C0201]
8C1093  10P-50-N-S2-MU  [C0201]
8R168  42.2-1-S2  [R0201]
8R170  42.2-1-S2  [R0201]
8R172  0-5-S2  [R0201]
8R176  42.2-1-S2  [R0201]
8R178  42.2-1-S2  [R0201]
8R180  42.2-1-S2  [R0201]
8R182  42.2-1-S2  [R0201]
8R234  0-1-S4-YA  [R0402]
8R646  42.2-1-S2  [R0201]
8R647  42.2-1-S2  [R0201]
8R659  10K-1-S2-WA  [R0201]
8R661  4.7K-1-S2  [R0201]
8R662  0-5-S2  [R0201]
8R663  4.7K-1-S2  [R0201]
8R664  42.2-1-S2  [R0201]
8R666  42.2-1-S2  [R0201]
8R672  10K-1-S2-WA  [R0201]
8R1088  42.2-1-S2  [R0201]
8R1089  42.2-1-S2  [R0201]
8R1098  4.7K-1-S2  [R0201]
8R1099  42.2-1-S2  [R0201]
8R1100  42.2-1-S2  [R0201]
8R1101  4.7K-1-S2  [R0201]
8R1102  0-5-S2  [R0201]
8R1103  42.2-1-S2  [R0201]
8R1104  0-5-S2  [R0201]
8R1105  10K-1-S2-WA  [R0201]
8R1106  42.2-1-S2  [R0201]
8R1107  42.2-1-S2  [R0201]
8R1108  10K-1-S2-WA  [R0201]
8R1109  42.2-1-S2  [R0201]
8R1110  42.2-1-S2  [R0201]
8R1111  42.2-1-S2  [R0201]
8R1114  42.2-1-S2  [R0201]
8R1115  42.2-1-S2  [R0201]
8R1117  0-1-S4-YA  [R0402]
8R1118  0-1-S4-YA  [R0402]
8R1119  0-1-S4-YA  [R0402]
8U408  CBTL06GP213EE-TFBGA50  [TFBGA9X9_50P_0P5MM]
8U409  CBTL06GP213EE-TFBGA50  [TFBGA9X9_50P_0P5MM]
8U455  CBTL06GP213EE-TFBGA50  [TFBGA9X9_50P_0P5MM]
8U456  CBTL06GP213EE-TFBGA50  [TFBGA9X9_50P_0P5MM]
SITE8  I6K51D-BGA290-9X7  [SK_TFBGA7X9_290P_0P4MM_JG]  (sections A,B,C,D,E,F,G,H,I,J,K,L,M,N,O)

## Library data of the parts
SITE6-SITE8 = I6K51D-BGA290-9X7
6BDB5 6BDB8 7BDB5 7BDB8 8BDB5 8BDB8 = BD120-1.5A-S4-MU: KAIROSNAME: BDB5
6BDB6 6BDB7 7BDB6 7BDB7 8BDB6 8BDB7 = BD120-1.5A-S4-MU: KAIROSNAME: BDB6
6C302 6C318 6C1088 6C1093 7C302 7C318 7C1088 7C1093 8C302 8C318 8C1088 8C1093 = 10P-50-N-S2-MU: KAIROSNAME: C318
6C309 6C1086 7C309 7C1086 8C309 8C1086 = 10P-50-N-S2-MU: KAIROSNAME: C309
6C310 6C1087 7C310 7C1087 8C310 8C1087 = 10P-50-N-S2-MU: KAIROSNAME: C310
6C320 6C1091 7C320 7C1091 8C320 8C1091 = 10P-50-N-S2-MU: KAIROSNAME: C320
6C922 6C1090 7C922 7C1090 8C922 8C1090 = 0.1U-16-X-S4-MU: KAIROSNAME: C922
6C923 6C1089 7C923 7C1089 8C923 8C1089 = 0.1U-16-X-S4-MU: KAIROSNAME: C923
6C924 7C924 8C924 = 10P-50-N-S2-MU: KAIROSNAME: C924
6R168 6R1099 7R168 7R1099 8R168 8R1099 = 42.2-1-S2: KAIROSNAME: R168
6R170 6R1100 7R170 7R1100 8R170 8R1100 = 42.2-1-S2: KAIROSNAME: R170
6R172 6R1104 7R172 7R1104 8R172 8R1104 = 0-5-S2: KAIROSNAME: R172
6R176 6R1089 6R1106 6R1115 7R176 7R1089 7R1106 7R1115 8R176 8R1089 8R1106 8R1115 = 42.2-1-S2: KAIROSNAME: R176
6R178 6R1088 6R1103 6R1114 7R178 7R1088 7R1103 7R1114 8R178 8R1088 8R1103 8R1114 = 42.2-1-S2: KAIROSNAME: R178
6R180 6R1110 7R180 7R1110 8R180 8R1110 = 42.2-1-S2: KAIROSNAME: R180
6R182 6R1111 7R182 7R1111 8R182 8R1111 = 42.2-1-S2: KAIROSNAME: R182
6R234 6R1117-6R1119 7R234 7R1117-7R1119 8R234 8R1117-8R1119 = 0-1-S4-YA
6R646 6R1107 7R646 7R1107 8R646 8R1107 = 42.2-1-S2: KAIROSNAME: R646
6R647 6R1109 7R647 7R1109 8R647 8R1109 = 42.2-1-S2: KAIROSNAME: R647
6R659 6R1105 7R659 7R1105 8R659 8R1105 = 10K-1-S2-WA: KAIROSNAME: R659
6R661 6R1101 7R661 7R1101 8R661 8R1101 = 4.7K-1-S2: KAIROSNAME: R661
6R662 6R1102 7R662 7R1102 8R662 8R1102 = 0-5-S2: KAIROSNAME: R662
6R663 6R1098 7R663 7R1098 8R663 8R1098 = 4.7K-1-S2: KAIROSNAME: R663
6R664 7R664 8R664 = 42.2-1-S2: KAIROSNAME: R664
6R666 7R666 8R666 = 42.2-1-S2: KAIROSNAME: R666
6R672 6R1108 7R672 7R1108 8R672 8R1108 = 10K-1-S2-WA: KAIROSNAME: R672
6U408 6U455 7U408 7U455 8U408 8U455 = CBTL06GP213EE-TFBGA50: KAIROSNAME: U408
6U409 6U456 7U409 7U456 8U409 8U456 = CBTL06GP213EE-TFBGA50: KAIROSNAME: U409
7CA1 8CA1 = 0.1U-16-X-S4-MU: KAIROSNAME: CA1
7CA2 8CA2 = 10U-25-X7R-SA: KAIROSNAME: CA2
7CA7 8CA7 = 10U-25-X7R-SA: KAIROSNAME: CA7
7CA8 8CA8 = 0.1U-16-X-S4-MU: KAIROSNAME: CA8
7CA19 8CA19 = 470U-25-E-S10.4X10.4: KAIROSNAME: CA19
7CA20 7CA34 7CA38 8CA20 8CA34 8CA38 = 10U-25-X7R-SA: KAIROSNAME: CA20
7CA21 7CA35 7CA39 8CA21 8CA35 8CA39 = 0.1U-16-X-S4-MU: KAIROSNAME: CA21
7CA22 8CA22 = 10U-25-X7R-SA: KAIROSNAME: CA22
7CA23 8CA23 = 0.1U-16-X-S4-MU: KAIROSNAME: CA23
7CA24 7CA37 8CA24 8CA37 = 10U-25-X7R-SA: KAIROSNAME: CA24
7CA25 7CA36 8CA25 8CA36 = 0.1U-16-X-S4-MU: KAIROSNAME: CA25
7CA26 8CA26 = 10U-25-X7R-SA: KAIROSNAME: CA26
7CA27 8CA27 = 0.1U-16-X-S4-MU: KAIROSNAME: CA27
7CC1 7CC14 7CC16 7CC130 7CC214-7CC219 8CC1 8CC14 8CC16 8CC130 8CC214-8CC219 = 0.1U-16-X7S-S2-MU: KAIROSNAME: CC1
7CC2 7CC13 7CC15 8CC2 8CC13 8CC15 = 0.1U-16-X7S-S2-MU: KAIROSNAME: CC2
7CC3 8CC3 = 0.1U-16-X7S-S2-MU: KAIROSNAME: CC3
7CC4 8CC4 = 0.1U-16-X7S-S2-MU: KAIROSNAME: CC4
7CC5 8CC5 = 0.1U-16-X7S-S2-MU: KAIROSNAME: CC5
7CC6 8CC6 = 0.1U-16-X7S-S2-MU: KAIROSNAME: CC6
7CC7 8CC7 = 0.1U-16-X7S-S2-MU: KAIROSNAME: CC7
7CC8 8CC8 = 0.1U-16-X7S-S2-MU: KAIROSNAME: CC8
7CC9 8CC9 = 0.1U-16-X7S-S2-MU: KAIROSNAME: CC9
7CC12 8CC12 = 0.1U-16-X7S-S2-MU: KAIROSNAME: CC12
7CC70 8CC70 = 0.1U-16-X7S-S2-MU: KAIROSNAME: CC70
7CC71 8CC71 = 0.1U-16-X7S-S2-MU: KAIROSNAME: CC71
7CC73 8CC73 = 0.1U-16-X7S-S2-MU: KAIROSNAME: CC73
7CC84 8CC84 = 0.1U-16-X7S-S2-MU: KAIROSNAME: CC84
7CC85 7CC182 7CC202 7CC220 8CC85 8CC182 8CC202 8CC220 = 0.1U-16-X7S-S2-MU: KAIROSNAME: CC85
7CC86 8CC86 = 0.1U-16-X7S-S2-MU: KAIROSNAME: CC86
7CC87 8CC87 = 0.1U-16-X7S-S2-MU: KAIROSNAME: CC87
7CC88 7CC90-7CC92 8CC88 8CC90-8CC92 = 0.1U-16-X7S-S2-MU: KAIROSNAME: CC88
7CC89 8CC89 = 0.1U-16-X7S-S2-MU: KAIROSNAME: CC89
7CC96 8CC96 = 0.1U-16-X7S-S2-MU: KAIROSNAME: CC96
7CC101 7CC213 8CC101 8CC213 = 0.1U-16-X7S-S2-MU: KAIROSNAME: CC101
7CC103 7CC211 8CC103 8CC211 = 0.1U-16-X7S-S2-MU: KAIROSNAME: CC103
7CC105 7CC212 8CC105 8CC212 = 0.1U-16-X7S-S2-MU: KAIROSNAME: CC105
7CC112 8CC112 = 0.1U-16-X7S-S2-MU: KAIROSNAME: CC112
7CC195 8CC195 = 4.7U-25-X7R-S8-TY
7K96 8K96 = EC2-5NJ: KAIROSNAME: K95A
7SA1 7SA16 7SA17 7SA19 7SA21 7SA25 8SA1 8SA16 8SA17 8SA19 8SA21 8SA25 = SHORT: KAIROSNAME: SA1
7SA2 7SA15 7SA18 7SA20 7SA22 7SA26 8SA2 8SA15 8SA18 8SA20 8SA22 8SA26 = SHORT: KAIROSNAME: SA2
7SA7 8SA7 = SHORT: KAIROSNAME: SA7
7SA8 8SA8 = SHORT: KAIROSNAME: SA8
7SA9 7SA23 8SA9 8SA23 = SHORT: KAIROSNAME: SA9
7SA10 7SA24 8SA10 8SA24 = SHORT: KAIROSNAME: SA10
7TP_DPS1 8TP_DPS1 = TP01: KAIROSNAME: TP_DPS1
7TP_DPS2 8TP_DPS2 = TP01: KAIROSNAME: S1_DPS3
7TP_DPS3 7TP_DPS4 7TP_DPS9 8TP_DPS3 8TP_DPS4 8TP_DPS9 = TP01: KAIROSNAME: S1_DPS4
7TP_DPS5 8TP_DPS5 = TP01: KAIROSNAME: S1_DPS5
7TP_DPS6 8TP_DPS6 = TP01: KAIROSNAME: TP_DPS8
7TP_DPS7 7TP_DPS8 8TP_DPS7 8TP_DPS8 = TP01: KAIROSNAME: TP_DPS2

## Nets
DGND: 6C302.2 6C309.2 6C310.2 6C318.2 6C320.2 6C922.1 6C923.1 6C924.2 6C1086.2 6C1087.2 6C1088.2 6C1089.1 6C1090.1 6C1091.2 6C1093.2 6R659.2 6R672.2 6R1105.2 6R1108.2 6U408.B3(GND) 6U408.C8(GND) 6U408.G2(GND) 6U408.G8(GND) 6U408.H4(GND) 6U408.H7(GND) 6U409.B3(GND) 6U409.C8(GND) 6U409.G2(GND) 6U409.G8(GND) 6U409.H4(GND) 6U409.H7(GND) 6U455.B3(GND) 6U455.C8(GND) 6U455.G2(GND) 6U455.G8(GND) 6U455.H4(GND) 6U455.H7(GND) 6U456.B3(GND) 6U456.C8(GND) 6U456.G2(GND) 6U456.G8(GND) 6U456.H4(GND) 6U456.H7(GND) 7C302.2 7C309.2 7C310.2 7C318.2 7C320.2 7C922.1 7C923.1 7C924.2 7C1086.2 7C1087.2 7C1088.2 7C1089.1 7C1090.1 7C1091.2 7C1093.2 7CA1.2 7CA2.2 7CA7.2 7CA8.2 7CA19.2 7CA20.2 7CA21.2 7CA22.2 7CA23.2 7CA24.2 7CA25.2 7CA26.2 7CA27.2 7CA34.2 7CA35.2 7CA36.2 7CA37.2 7CA38.2 7CA39.2 7CC1.2 7CC2.2 7CC3.2 7CC4.2 7CC5.2 7CC6.2 7CC7.2 7CC8.2 7CC9.2 7CC12.2 7CC13.2 7CC14.2 7CC15.2 7CC16.2 7CC70.2 7CC71.2 7CC73.2 7CC84.2 7CC85.2 7CC86.2 7CC87.2 7CC88.2 7CC89.2 7CC90.2 7CC91.2 7CC92.2 7CC96.2 7CC101.2 7CC103.2 7CC105.2 7CC112.2 7CC130.2 7CC182.2 7CC195.2 7CC202.2 7CC211.2 7CC212.2 7CC213.2 7CC214.2 7CC215.2 7CC216.2 7CC217.2 7CC218.2 7CC219.2 7CC220.2 7R659.2 7R672.2 7R1105.2 7R1108.2 7SA2.1 7SA7.1 7SA10.1 7SA15.1 7SA18.1 7SA20.1 7SA22.1 7SA24.1 7SA26.1 7U408.B3(GND) 7U408.C8(GND) 7U408.G2(GND) 7U408.G8(GND) 7U408.H4(GND) 7U408.H7(GND) 7U409.B3(GND) 7U409.C8(GND) 7U409.G2(GND) 7U409.G8(GND) 7U409.H4(GND) 7U409.H7(GND) 7U455.B3(GND) 7U455.C8(GND) 7U455.G2(GND) 7U455.G8(GND) 7U455.H4(GND) 7U455.H7(GND) 7U456.B3(GND) 7U456.C8(GND) 7U456.G2(GND) 7U456.G8(GND) 7U456.H4(GND) 7U456.H7(GND) 8C302.2 8C309.2 8C310.2 8C318.2 8C320.2 8C922.1 8C923.1 8C924.2 8C1086.2 8C1087.2 8C1088.2 8C1089.1 8C1090.1 8C1091.2 8C1093.2 8CA1.2 8CA2.2 8CA7.2 8CA8.2 8CA19.2 8CA20.2 8CA21.2 8CA22.2 8CA23.2 8CA24.2 8CA25.2 8CA26.2 8CA27.2 8CA34.2 8CA35.2 8CA36.2 8CA37.2 8CA38.2 8CA39.2 8CC1.2 8CC2.2 8CC3.2 8CC4.2 8CC5.2 8CC6.2 8CC7.2 8CC8.2 8CC9.2 8CC12.2 8CC13.2 8CC14.2 8CC15.2 8CC16.2 8CC70.2 8CC71.2 8CC73.2 8CC84.2 8CC85.2 8CC86.2 8CC87.2 8CC88.2 8CC89.2 8CC90.2 8CC91.2 8CC92.2 8CC96.2 8CC101.2 8CC103.2 8CC105.2 8CC112.2 8CC130.2 8CC182.2 8CC195.2 8CC202.2 8CC211.2 8CC212.2 8CC213.2 8CC214.2 8CC215.2 8CC216.2 8CC217.2 8CC218.2 8CC219.2 8CC220.2 8R659.2 8R672.2 8R1105.2 8R1108.2 8SA2.1 8SA7.1 8SA10.1 8SA15.1 8SA18.1 8SA20.1 8SA22.1 8SA24.1 8SA26.1 8U408.B3(GND) 8U408.C8(GND) 8U408.G2(GND) 8U408.G8(GND) 8U408.H4(GND) 8U408.H7(GND) 8U409.B3(GND) 8U409.C8(GND) 8U409.G2(GND) 8U409.G8(GND) 8U409.H4(GND) 8U409.H7(GND) 8U455.B3(GND) 8U455.C8(GND) 8U455.G2(GND) 8U455.G8(GND) 8U455.H4(GND) 8U455.H7(GND) 8U456.B3(GND) 8U456.C8(GND) 8U456.G2(GND) 8U456.G8(GND) 8U456.H4(GND) 8U456.H7(GND) ; also on sheet 6 7 8 9 10 11 12 13 14 17 18 19 20 21 22 23 24 25 26 27 28 30 31 32 33 34 35 36 37
6SA_CBIT_S20: 6R662.2 6R1102.2
6SA_CBIT_S29: 6R172.2 6R1104.2
7SA_CBIT_R96: 7K96.12(V-)
7SA_CBIT_S20: 7R662.2 7R1102.2
7SA_CBIT_S29: 7R172.2 7R1104.2
8SA_CBIT_R96: 8K96.12(V-)
8SA_CBIT_S20: 8R662.2 8R1102.2
8SA_CBIT_S29: 8R172.2 8R1104.2
S6_3V3_RX0_MIPI: 6BDB5.2 6C922.2 6R661.2 6U408.A2(VDD) 6U408.J4(VDD)
S6_3V3_RX1_MIPI: 6BDB6.2 6C923.2 6R663.2 6U409.A2(VDD) 6U409.J4(VDD)
S6_3V3_TX0_MIPI: 6BDB8.2 6C1090.2 6R1101.2 6U455.A2(VDD) 6U455.J4(VDD)
S6_3V3_TX1_MIPI: 6BDB7.2 6C1089.2 6R1098.2 6U456.A2(VDD) 6U456.J4(VDD)
S6_Mpdch37+: 6U408.B8(DIN2_0+)
S6_Mpdch37-: 6U408.B9(DIN2_0-)
S6_Mpdch38+: 6U455.B8(DIN2_0+)
S6_Mpdch38-: 6U455.B9(DIN2_0-)
S6_Mpdch39+: 6U408.D8(DIN2_1+)
S6_Mpdch39-: 6U408.D9(DIN2_1-)
S6_Mpdch40+: 6U455.D8(DIN2_1+)
S6_Mpdch40-: 6U455.D9(DIN2_1-)
S6_Mpdch41+: 6U408.E8(DIN2_2+)
S6_Mpdch41-: 6U408.E9(DIN2_2-)
S6_Mpdch42+: 6U455.E8(DIN2_2+)
S6_Mpdch42-: 6U455.E9(DIN2_2-)
S6_Mpdch43+: 6U409.B8(DIN2_0+)
S6_Mpdch43-: 6U409.B9(DIN2_0-)
S6_Mpdch44+: 6U456.B8(DIN2_0+)
S6_Mpdch44-: 6U456.B9(DIN2_0-)
S6_Mpdch45+: 6U409.D8(DIN2_1+)
S6_Mpdch45-: 6U409.D9(DIN2_1-)
S6_Mpdch46+: 6U456.D8(DIN2_1+)
S6_Mpdch46-: 6U456.D9(DIN2_1-)
S6_Mpdch47+: 6U409.E8(DIN2_2+)
S6_Mpdch47-: 6U409.E9(DIN2_2-)
S6_MUX_3V3: 6R234.2 6R1117.2 6R1118.2 6R1119.2 ; also on sheet 36
S6_OUT_RX0_CH0_ABC_CASE+: 6U408.B2(DOUT_0+) SITE6.B10(PAD_OUTP_RX0_CH[0])
S6_OUT_RX0_CH0_ABC_CASE-: 6U408.B1(DOUT_0-) SITE6.A10(PAD_OUTN_RX0_CH[0])
S6_OUT_RX0_CH0_B_CASE+: 6R647.1 6U408.B4(DIN1_0+)
S6_OUT_RX0_CH0_B_CASE-: 6R646.1 6U408.A4(DIN1_0-)
S6_OUT_RX0_CH0_C_CASE: 6C309.1 6R646.2 6R647.2
S6_OUT_RX0_CH1_ABC_CASE+: 6U408.D2(DOUT_1+) SITE6.B9(PAD_OUTP_RX0_CH[1])
S6_OUT_RX0_CH1_ABC_CASE-: 6U408.D1(DOUT_1-) SITE6.B8(PAD_OUTN_RX0_CH[1])
S6_OUT_RX0_CH1_B_CASE+: 6R168.1 6U408.B5(DIN1_1+)
S6_OUT_RX0_CH1_B_CASE-: 6R170.1 6U408.A5(DIN1_1-)
S6_OUT_RX0_CH1_C_CASE: 6C310.1 6R168.2 6R170.2
S6_OUT_RX0_CH2_ABC_CASE+: 6U408.E2(DOUT_2+) SITE6.A8(PAD_OUTP_RX0_CH[2])
S6_OUT_RX0_CH2_ABC_CASE-: 6U408.E1(DOUT_2-) SITE6.B7(PAD_OUTN_RX0_CH[2])
S6_OUT_RX0_CH2_B_CASE+: 6R176.1 6U408.B6(DIN1_2+)
S6_OUT_RX0_CH2_B_CASE-: 6R178.1 6U408.A6(DIN1_2-)
S6_OUT_RX0_CH2_C_CASE: 6C318.1 6R176.2 6R178.2
S6_OUT_RX0_CH3_ABC_CASE+: 6U409.B2(DOUT_0+) SITE6.B6(PAD_OUTP_RX0_CH[3])
S6_OUT_RX0_CH3_ABC_CASE-: 6U409.B1(DOUT_0-) SITE6.A6(PAD_OUTN_RX0_CH[3])
S6_OUT_RX0_CH3_B_CASE+: 6R1089.1 6U409.B4(DIN1_0+)
S6_OUT_RX0_CH3_B_CASE-: 6R1088.1 6U409.A4(DIN1_0-)
S6_OUT_RX0_CH3_C_CASE: 6C302.1 6R1088.2 6R1089.2
S6_OUT_RX0_CH4_ABC_CASE+: 6U409.D2(DOUT_1+) SITE6.B5(PAD_OUTP_RX0_CH[4])
S6_OUT_RX0_CH4_ABC_CASE-: 6U409.D1(DOUT_1-) SITE6.B4(PAD_OUTN_RX0_CH[4])
S6_OUT_RX0_CH4_B_CASE+: 6R180.1 6U409.B5(DIN1_1+)
S6_OUT_RX0_CH4_B_CASE-: 6R182.1 6U409.A5(DIN1_1-)
S6_OUT_RX0_CH4_C_CASE: 6C320.1 6R180.2 6R182.2
S6_OUT_RX0_CH5_ABC_CASE+: 6U409.E2(DOUT_2+) SITE6.A4(PAD_OUTP_RX0_CH[5])
S6_OUT_RX0_CH5_ABC_CASE-: 6U409.E1(DOUT_2-) SITE6.B3(PAD_OUTN_RX0_CH[5])
S6_OUT_RX0_CH5_B_CASE+: 6R666.1 6U409.B6(DIN1_2+)
S6_OUT_RX0_CH5_B_CASE-: 6R664.1 6U409.A6(DIN1_2-)
S6_OUT_RX0_CH5_C_CASE: 6C924.1 6R664.2 6R666.2
S6_OUT_TX0_CH0_ABC_CASE+: 6U455.B2(DOUT_0+) SITE6.A2(PAD_OUTP_TX0_CH[0])
S6_OUT_TX0_CH0_ABC_CASE-: 6U455.B1(DOUT_0-) SITE6.B1(PAD_OUTN_TX0_CH[0])
S6_OUT_TX0_CH0_B_CASE+: 6R1109.1 6U455.B4(DIN1_0+)
S6_OUT_TX0_CH0_B_CASE-: 6R1107.1 6U455.A4(DIN1_0-)
S6_OUT_TX0_CH0_C_CASE: 6C1086.1 6R1107.2 6R1109.2
S6_OUT_TX0_CH1_ABC_CASE+: 6U455.D2(DOUT_1+) SITE6.C1(PAD_OUTP_TX0_CH[1])
S6_OUT_TX0_CH1_ABC_CASE-: 6U455.D1(DOUT_1-) SITE6.C2(PAD_OUTN_TX0_CH[1])
S6_OUT_TX0_CH1_B_CASE+: 6R1099.1 6U455.B5(DIN1_1+)
S6_OUT_TX0_CH1_B_CASE-: 6R1100.1 6U455.A5(DIN1_1-)
S6_OUT_TX0_CH1_C_CASE: 6C1087.1 6R1099.2 6R1100.2
S6_OUT_TX0_CH2_ABC_CASE+: 6U455.E2(DOUT_2+) SITE6.D2(PAD_OUTP_TX0_CH[2])
S6_OUT_TX0_CH2_ABC_CASE-: 6U455.E1(DOUT_2-) SITE6.E1(PAD_OUTN_TX0_CH[2])
S6_OUT_TX0_CH2_B_CASE+: 6R1106.1 6U455.B6(DIN1_2+)
S6_OUT_TX0_CH2_B_CASE-: 6R1103.1 6U455.A6(DIN1_2-)
S6_OUT_TX0_CH2_C_CASE: 6C1088.1 6R1103.2 6R1106.2
S6_OUT_TX0_CH3_ABC_CASE+: 6U456.B2(DOUT_0+) SITE6.E2(PAD_OUTP_TX0_CH[3])
S6_OUT_TX0_CH3_ABC_CASE-: 6U456.B1(DOUT_0-) SITE6.F2(PAD_OUTN_TX0_CH[3])
S6_OUT_TX0_CH3_B_CASE+: 6R1115.1 6U456.B4(DIN1_0+)
S6_OUT_TX0_CH3_B_CASE-: 6R1114.1 6U456.A4(DIN1_0-)
S6_OUT_TX0_CH3_C_CASE: 6C1093.1 6R1114.2 6R1115.2
S6_OUT_TX0_CH4_ABC_CASE+: 6U456.D2(DOUT_1+) SITE6.G1(PAD_OUTP_TX0_CH[4])
S6_OUT_TX0_CH4_ABC_CASE-: 6U456.D1(DOUT_1-) SITE6.G2(PAD_OUTN_TX0_CH[4])
S6_OUT_TX0_CH4_B_CASE+: 6R1110.1 6U456.B5(DIN1_1+)
S6_OUT_TX0_CH4_B_CASE-: 6R1111.1 6U456.A5(DIN1_1-)
S6_OUT_TX0_CH4_C_CASE: 6C1091.1 6R1110.2 6R1111.2
S7_3V3_RX0_MIPI: 7BDB5.2 7C922.2 7R661.2 7U408.A2(VDD) 7U408.J4(VDD)
S7_3V3_RX1_MIPI: 7BDB6.2 7C923.2 7R663.2 7U409.A2(VDD) 7U409.J4(VDD)
S7_3V3_TX0_MIPI: 7BDB8.2 7C1090.2 7R1101.2 7U455.A2(VDD) 7U455.J4(VDD)
S7_3V3_TX1_MIPI: 7BDB7.2 7C1089.2 7R1098.2 7U456.A2(VDD) 7U456.J4(VDD)
S7_B_DCH001: 7CC195.1 SITE7.M18(VDDP18_LDO_P0)
S7_DPS3: 7CA20.1 7CA21.1 7CC84.1 7CC85.1 7CC86.1 7CC87.1 7CC88.1 7CC89.1 7CC90.1 7CC91.1 7CC92.1 7SA17.1 7TP_DPS3.1(TP) SITE7.F4(VDDP18_P1) SITE7.F17(AVDD18_NODIE) SITE7.G5(AVDD18_MIPI_TX) SITE7.H4(AVDD18_USB) SITE7.J18(AVDD18_OTP) SITE7.L5(AVDD18_AUD) SITE7.R11(AVDD18_PLL_DDR) SITE7.R14(VDD1_DRAM[0]) SITE7.R15(VDD1_DRAM[1])
S7_DPS4: 7CA34.1 7CA35.1 7CC182.1 7CC202.1 7SA19.1 7TP_DPS4.1(TP) SITE7.H19(AVDD33_ETH) SITE7.J5(AVDD33_USB)
S7_Mpdch37+: 7U408.B8(DIN2_0+)
S7_Mpdch37-: 7U408.B9(DIN2_0-)
S7_Mpdch38+: 7U455.B8(DIN2_0+)
S7_Mpdch38-: 7U455.B9(DIN2_0-)
S7_Mpdch39+: 7U408.D8(DIN2_1+)
S7_Mpdch39-: 7U408.D9(DIN2_1-)
S7_Mpdch40+: 7U455.D8(DIN2_1+)
S7_Mpdch40-: 7U455.D9(DIN2_1-)
S7_Mpdch41+: 7U408.E8(DIN2_2+)
S7_Mpdch41-: 7U408.E9(DIN2_2-)
S7_Mpdch42+: 7U455.E8(DIN2_2+)
S7_Mpdch42-: 7U455.E9(DIN2_2-)
S7_Mpdch43+: 7U409.B8(DIN2_0+)
S7_Mpdch43-: 7U409.B9(DIN2_0-)
S7_Mpdch44+: 7U456.B8(DIN2_0+)
S7_Mpdch44-: 7U456.B9(DIN2_0-)
S7_Mpdch45+: 7U409.D8(DIN2_1+)
S7_Mpdch45-: 7U409.D9(DIN2_1-)
S7_Mpdch46+: 7U456.D8(DIN2_1+)
S7_Mpdch46-: 7U456.D9(DIN2_1-)
S7_Mpdch47+: 7U409.E8(DIN2_2+)
S7_Mpdch47-: 7U409.E9(DIN2_2-)
S7_MUX_3V3: 7R234.2 7R1117.2 7R1118.2 7R1119.2 ; also on sheet 35
S7_OUT_RX0_CH0_ABC_CASE+: 7U408.B2(DOUT_0+) SITE7.B10(PAD_OUTP_RX0_CH[0])
S7_OUT_RX0_CH0_ABC_CASE-: 7U408.B1(DOUT_0-) SITE7.A10(PAD_OUTN_RX0_CH[0])
S7_OUT_RX0_CH0_B_CASE+: 7R647.1 7U408.B4(DIN1_0+)
S7_OUT_RX0_CH0_B_CASE-: 7R646.1 7U408.A4(DIN1_0-)
S7_OUT_RX0_CH0_C_CASE: 7C309.1 7R646.2 7R647.2
S7_OUT_RX0_CH1_ABC_CASE+: 7U408.D2(DOUT_1+) SITE7.B9(PAD_OUTP_RX0_CH[1])
S7_OUT_RX0_CH1_ABC_CASE-: 7U408.D1(DOUT_1-) SITE7.B8(PAD_OUTN_RX0_CH[1])
S7_OUT_RX0_CH1_B_CASE+: 7R168.1 7U408.B5(DIN1_1+)
S7_OUT_RX0_CH1_B_CASE-: 7R170.1 7U408.A5(DIN1_1-)
S7_OUT_RX0_CH1_C_CASE: 7C310.1 7R168.2 7R170.2
S7_OUT_RX0_CH2_ABC_CASE+: 7U408.E2(DOUT_2+) SITE7.A8(PAD_OUTP_RX0_CH[2])
S7_OUT_RX0_CH2_ABC_CASE-: 7U408.E1(DOUT_2-) SITE7.B7(PAD_OUTN_RX0_CH[2])
S7_OUT_RX0_CH2_B_CASE+: 7R176.1 7U408.B6(DIN1_2+)
S7_OUT_RX0_CH2_B_CASE-: 7R178.1 7U408.A6(DIN1_2-)
S7_OUT_RX0_CH2_C_CASE: 7C318.1 7R176.2 7R178.2
S7_OUT_RX0_CH3_ABC_CASE+: 7U409.B2(DOUT_0+) SITE7.B6(PAD_OUTP_RX0_CH[3])
S7_OUT_RX0_CH3_ABC_CASE-: 7U409.B1(DOUT_0-) SITE7.A6(PAD_OUTN_RX0_CH[3])
S7_OUT_RX0_CH3_B_CASE+: 7R1089.1 7U409.B4(DIN1_0+)
S7_OUT_RX0_CH3_B_CASE-: 7R1088.1 7U409.A4(DIN1_0-)
S7_OUT_RX0_CH3_C_CASE: 7C302.1 7R1088.2 7R1089.2
S7_OUT_RX0_CH4_ABC_CASE+: 7U409.D2(DOUT_1+) SITE7.B5(PAD_OUTP_RX0_CH[4])
S7_OUT_RX0_CH4_ABC_CASE-: 7U409.D1(DOUT_1-) SITE7.B4(PAD_OUTN_RX0_CH[4])
S7_OUT_RX0_CH4_B_CASE+: 7R180.1 7U409.B5(DIN1_1+)
S7_OUT_RX0_CH4_B_CASE-: 7R182.1 7U409.A5(DIN1_1-)
S7_OUT_RX0_CH4_C_CASE: 7C320.1 7R180.2 7R182.2
S7_OUT_RX0_CH5_ABC_CASE+: 7U409.E2(DOUT_2+) SITE7.A4(PAD_OUTP_RX0_CH[5])
S7_OUT_RX0_CH5_ABC_CASE-: 7U409.E1(DOUT_2-) SITE7.B3(PAD_OUTN_RX0_CH[5])
S7_OUT_RX0_CH5_B_CASE+: 7R666.1 7U409.B6(DIN1_2+)
S7_OUT_RX0_CH5_B_CASE-: 7R664.1 7U409.A6(DIN1_2-)
S7_OUT_RX0_CH5_C_CASE: 7C924.1 7R664.2 7R666.2
S7_OUT_TX0_CH0_ABC_CASE+: 7U455.B2(DOUT_0+) SITE7.A2(PAD_OUTP_TX0_CH[0])
S7_OUT_TX0_CH0_ABC_CASE-: 7U455.B1(DOUT_0-) SITE7.B1(PAD_OUTN_TX0_CH[0])
S7_OUT_TX0_CH0_B_CASE+: 7R1109.1 7U455.B4(DIN1_0+)
S7_OUT_TX0_CH0_B_CASE-: 7R1107.1 7U455.A4(DIN1_0-)
S7_OUT_TX0_CH0_C_CASE: 7C1086.1 7R1107.2 7R1109.2
S7_OUT_TX0_CH1_ABC_CASE+: 7U455.D2(DOUT_1+) SITE7.C1(PAD_OUTP_TX0_CH[1])
S7_OUT_TX0_CH1_ABC_CASE-: 7U455.D1(DOUT_1-) SITE7.C2(PAD_OUTN_TX0_CH[1])
S7_OUT_TX0_CH1_B_CASE+: 7R1099.1 7U455.B5(DIN1_1+)
S7_OUT_TX0_CH1_B_CASE-: 7R1100.1 7U455.A5(DIN1_1-)
S7_OUT_TX0_CH1_C_CASE: 7C1087.1 7R1099.2 7R1100.2
S7_OUT_TX0_CH2_ABC_CASE+: 7U455.E2(DOUT_2+) SITE7.D2(PAD_OUTP_TX0_CH[2])
S7_OUT_TX0_CH2_ABC_CASE-: 7U455.E1(DOUT_2-) SITE7.E1(PAD_OUTN_TX0_CH[2])
S7_OUT_TX0_CH2_B_CASE+: 7R1106.1 7U455.B6(DIN1_2+)
S7_OUT_TX0_CH2_B_CASE-: 7R1103.1 7U455.A6(DIN1_2-)
S7_OUT_TX0_CH2_C_CASE: 7C1088.1 7R1103.2 7R1106.2
S7_OUT_TX0_CH3_ABC_CASE+: 7U456.B2(DOUT_0+) SITE7.E2(PAD_OUTP_TX0_CH[3])
S7_OUT_TX0_CH3_ABC_CASE-: 7U456.B1(DOUT_0-) SITE7.F2(PAD_OUTN_TX0_CH[3])
S7_OUT_TX0_CH3_B_CASE+: 7R1115.1 7U456.B4(DIN1_0+)
S7_OUT_TX0_CH3_B_CASE-: 7R1114.1 7U456.A4(DIN1_0-)
S7_OUT_TX0_CH3_C_CASE: 7C1093.1 7R1114.2 7R1115.2
S7_OUT_TX0_CH4_ABC_CASE+: 7U456.D2(DOUT_1+) SITE7.G1(PAD_OUTP_TX0_CH[4])
S7_OUT_TX0_CH4_ABC_CASE-: 7U456.D1(DOUT_1-) SITE7.G2(PAD_OUTN_TX0_CH[4])
S7_OUT_TX0_CH4_B_CASE+: 7R1110.1 7U456.B5(DIN1_1+)
S7_OUT_TX0_CH4_B_CASE-: 7R1111.1 7U456.A5(DIN1_1-)
S7_OUT_TX0_CH4_C_CASE: 7C1091.1 7R1110.2 7R1111.2
S7_PWR_F001: 7CA26.1 7CA27.1 7CC112.1 7SA16.1 7TP_DPS2.1(TP) SITE7.F15(DVDD_NODIE)
S7_PWR_F004: 7CA22.1 7CA23.1 7CC96.1 7SA21.1 7TP_DPS5.1(TP) SITE7.E10(AVDD33_RTC)
S7_PWR_F005: 7CA7.1 7CA8.1 7CC70.1 7CC71.1 7CC73.1 7SA8.1 7TP_DPS6.1(TP) SITE7.G18(VDDP3318_PM) SITE7.N17(VDDP3318_P0) SITE7.P3(VDDP3318_P2)
S7_PWR_F006: 7CA24.1 7CA25.1 7CC101.1 7CC103.1 7CC105.1 7SA9.1 7TP_DPS7.1(TP) SITE7.T13(VDD2_DRAM[0]) SITE7.T14(VDD2_DRAM[1]) SITE7.U13(VDD2_DRAM[2])
S7_PWR_F007: 7CA36.1 7CA37.1 7CC211.1 7CC212.1 7CC213.1 7SA23.1 7TP_DPS8.1(TP) SITE7.T10(VDDQ_DRAM[0]) SITE7.T11(VDDQ_DRAM[1]) SITE7.U11(VDDQ_DRAM[2])
S7_PWR_F008: 7CA38.1 7CA39.1 7CC220.1 7SA25.1 7TP_DPS9.1(TP) SITE7.K19(AVDD18_XTAL)
S7_PWR_GS001: 7SA15.2
S7_PWR_GS002: 7SA18.2
S7_PWR_GS003: 7SA20.2
S7_PWR_GS004: 7SA22.2
S7_PWR_GS005: 7SA7.2
S7_PWR_GS006: 7SA10.2
S7_PWR_GS007: 7SA24.2
S7_PWR_GS008: 7SA26.2
S7_PWR_M_F001: 7CA1.1 7CA2.1 7CC1.1 7CC2.1 7CC3.1 7CC4.1 7CC5.1 7CC6.1 7CC7.1 7CC8.1 7CC9.1 7CC12.1 7CC13.1 7CC14.1 7CC15.1 7CC16.1 7CC130.1 7CC214.1 7CC215.1 7CC216.1 7CC217.1 7CC218.1 7CC219.1 7K96.4 7K96.9 7SA1.1 7TP_DPS1.1(TP) SITE7.F6(AVDDL_MIPI_RX) SITE7.F7(VDD_CPU[0]) SITE7.F8(VDD_CPU[1]) SITE7.G6(AVDDL_MIPI_TX) SITE7.G7(VDD_CPU[2]) SITE7.G8(VDD_CPU[3]) SITE7.G10(VDD[0]) SITE7.G11(VDD[1]) SITE7.H7(VDD_CPU[4]) SITE7.H8(VDD_CPU[5]) SITE7.H10(VDD[2]) SITE7.H11(VDD[3]) SITE7.H12(VDD[4]) SITE7.J10(VDD[5]) SITE7.J11(VDD[6]) SITE7.J12(VDD[7]) SITE7.J13(VDD[8]) SITE7.K10(VDD[9]) SITE7.K11(VDD[10]) SITE7.K12(VDD[11]) SITE7.K13(VDD[12])
S7_PWR_M_GS001: 7SA2.2
S7_PWR_M_S001: 7SA1.2
S7_PWR_S001: 7SA16.2
S7_PWR_S002: 7SA17.2
S7_PWR_S003: 7SA19.2
S7_PWR_S004: 7SA21.2
S7_PWR_S005: 7SA8.2
S7_PWR_S006: 7SA9.2
S7_PWR_S007: 7SA23.2
S7_PWR_S008: 7SA25.2
S8_3V3_RX0_MIPI: 8BDB5.2 8C922.2 8R661.2 8U408.A2(VDD) 8U408.J4(VDD)
S8_3V3_RX1_MIPI: 8BDB6.2 8C923.2 8R663.2 8U409.A2(VDD) 8U409.J4(VDD)
S8_3V3_TX0_MIPI: 8BDB8.2 8C1090.2 8R1101.2 8U455.A2(VDD) 8U455.J4(VDD)
S8_3V3_TX1_MIPI: 8BDB7.2 8C1089.2 8R1098.2 8U456.A2(VDD) 8U456.J4(VDD)
S8_B_DCH001: 8CC195.1 SITE8.M18(VDDP18_LDO_P0)
S8_DPS3: 8CA20.1 8CA21.1 8CC84.1 8CC85.1 8CC86.1 8CC87.1 8CC88.1 8CC89.1 8CC90.1 8CC91.1 8CC92.1 8SA17.1 8TP_DPS3.1(TP) SITE8.F4(VDDP18_P1) SITE8.F17(AVDD18_NODIE) SITE8.G5(AVDD18_MIPI_TX) SITE8.H4(AVDD18_USB) SITE8.J18(AVDD18_OTP) SITE8.L5(AVDD18_AUD) SITE8.R11(AVDD18_PLL_DDR) SITE8.R14(VDD1_DRAM[0]) SITE8.R15(VDD1_DRAM[1])
S8_DPS4: 8CA34.1 8CA35.1 8CC182.1 8CC202.1 8SA19.1 8TP_DPS4.1(TP) SITE8.H19(AVDD33_ETH) SITE8.J5(AVDD33_USB)
S8_Mpdch37+: 8U408.B8(DIN2_0+)
S8_Mpdch37-: 8U408.B9(DIN2_0-)
S8_Mpdch38+: 8U455.B8(DIN2_0+)
S8_Mpdch38-: 8U455.B9(DIN2_0-)
S8_Mpdch39+: 8U408.D8(DIN2_1+)
S8_Mpdch39-: 8U408.D9(DIN2_1-)
S8_Mpdch40+: 8U455.D8(DIN2_1+)
S8_Mpdch40-: 8U455.D9(DIN2_1-)
S8_Mpdch41+: 8U408.E8(DIN2_2+)
S8_Mpdch41-: 8U408.E9(DIN2_2-)
S8_Mpdch42+: 8U455.E8(DIN2_2+)
S8_Mpdch42-: 8U455.E9(DIN2_2-)
S8_Mpdch43+: 8U409.B8(DIN2_0+)
S8_Mpdch43-: 8U409.B9(DIN2_0-)
S8_Mpdch44+: 8U456.B8(DIN2_0+)
S8_Mpdch44-: 8U456.B9(DIN2_0-)
S8_Mpdch45+: 8U409.D8(DIN2_1+)
S8_Mpdch45-: 8U409.D9(DIN2_1-)
S8_Mpdch46+: 8U456.D8(DIN2_1+)
S8_Mpdch46-: 8U456.D9(DIN2_1-)
S8_Mpdch47+: 8U409.E8(DIN2_2+)
S8_Mpdch47-: 8U409.E9(DIN2_2-)
S8_MUX_3V3: 8R234.2 8R1117.2 8R1118.2 8R1119.2 ; also on sheet 37
S8_OUT_RX0_CH0_ABC_CASE+: 8U408.B2(DOUT_0+) SITE8.B10(PAD_OUTP_RX0_CH[0])
S8_OUT_RX0_CH0_ABC_CASE-: 8U408.B1(DOUT_0-) SITE8.A10(PAD_OUTN_RX0_CH[0])
S8_OUT_RX0_CH0_B_CASE+: 8R647.1 8U408.B4(DIN1_0+)
S8_OUT_RX0_CH0_B_CASE-: 8R646.1 8U408.A4(DIN1_0-)
S8_OUT_RX0_CH0_C_CASE: 8C309.1 8R646.2 8R647.2
S8_OUT_RX0_CH1_ABC_CASE+: 8U408.D2(DOUT_1+) SITE8.B9(PAD_OUTP_RX0_CH[1])
S8_OUT_RX0_CH1_ABC_CASE-: 8U408.D1(DOUT_1-) SITE8.B8(PAD_OUTN_RX0_CH[1])
S8_OUT_RX0_CH1_B_CASE+: 8R168.1 8U408.B5(DIN1_1+)
S8_OUT_RX0_CH1_B_CASE-: 8R170.1 8U408.A5(DIN1_1-)
S8_OUT_RX0_CH1_C_CASE: 8C310.1 8R168.2 8R170.2
S8_OUT_RX0_CH2_ABC_CASE+: 8U408.E2(DOUT_2+) SITE8.A8(PAD_OUTP_RX0_CH[2])
S8_OUT_RX0_CH2_ABC_CASE-: 8U408.E1(DOUT_2-) SITE8.B7(PAD_OUTN_RX0_CH[2])
S8_OUT_RX0_CH2_B_CASE+: 8R176.1 8U408.B6(DIN1_2+)
S8_OUT_RX0_CH2_B_CASE-: 8R178.1 8U408.A6(DIN1_2-)
S8_OUT_RX0_CH2_C_CASE: 8C318.1 8R176.2 8R178.2
S8_OUT_RX0_CH3_ABC_CASE+: 8U409.B2(DOUT_0+) SITE8.B6(PAD_OUTP_RX0_CH[3])
S8_OUT_RX0_CH3_ABC_CASE-: 8U409.B1(DOUT_0-) SITE8.A6(PAD_OUTN_RX0_CH[3])
S8_OUT_RX0_CH3_B_CASE+: 8R1089.1 8U409.B4(DIN1_0+)
S8_OUT_RX0_CH3_B_CASE-: 8R1088.1 8U409.A4(DIN1_0-)
S8_OUT_RX0_CH3_C_CASE: 8C302.1 8R1088.2 8R1089.2
S8_OUT_RX0_CH4_ABC_CASE+: 8U409.D2(DOUT_1+) SITE8.B5(PAD_OUTP_RX0_CH[4])
S8_OUT_RX0_CH4_ABC_CASE-: 8U409.D1(DOUT_1-) SITE8.B4(PAD_OUTN_RX0_CH[4])
S8_OUT_RX0_CH4_B_CASE+: 8R180.1 8U409.B5(DIN1_1+)
S8_OUT_RX0_CH4_B_CASE-: 8R182.1 8U409.A5(DIN1_1-)
S8_OUT_RX0_CH4_C_CASE: 8C320.1 8R180.2 8R182.2
S8_OUT_RX0_CH5_ABC_CASE+: 8U409.E2(DOUT_2+) SITE8.A4(PAD_OUTP_RX0_CH[5])
S8_OUT_RX0_CH5_ABC_CASE-: 8U409.E1(DOUT_2-) SITE8.B3(PAD_OUTN_RX0_CH[5])
S8_OUT_RX0_CH5_B_CASE+: 8R666.1 8U409.B6(DIN1_2+)
S8_OUT_RX0_CH5_B_CASE-: 8R664.1 8U409.A6(DIN1_2-)
S8_OUT_RX0_CH5_C_CASE: 8C924.1 8R664.2 8R666.2
S8_OUT_TX0_CH0_ABC_CASE+: 8U455.B2(DOUT_0+) SITE8.A2(PAD_OUTP_TX0_CH[0])
S8_OUT_TX0_CH0_ABC_CASE-: 8U455.B1(DOUT_0-) SITE8.B1(PAD_OUTN_TX0_CH[0])
S8_OUT_TX0_CH0_B_CASE+: 8R1109.1 8U455.B4(DIN1_0+)
S8_OUT_TX0_CH0_B_CASE-: 8R1107.1 8U455.A4(DIN1_0-)
S8_OUT_TX0_CH0_C_CASE: 8C1086.1 8R1107.2 8R1109.2
S8_OUT_TX0_CH1_ABC_CASE+: 8U455.D2(DOUT_1+) SITE8.C1(PAD_OUTP_TX0_CH[1])
S8_OUT_TX0_CH1_ABC_CASE-: 8U455.D1(DOUT_1-) SITE8.C2(PAD_OUTN_TX0_CH[1])
S8_OUT_TX0_CH1_B_CASE+: 8R1099.1 8U455.B5(DIN1_1+)
S8_OUT_TX0_CH1_B_CASE-: 8R1100.1 8U455.A5(DIN1_1-)
S8_OUT_TX0_CH1_C_CASE: 8C1087.1 8R1099.2 8R1100.2
S8_OUT_TX0_CH2_ABC_CASE+: 8U455.E2(DOUT_2+) SITE8.D2(PAD_OUTP_TX0_CH[2])
S8_OUT_TX0_CH2_ABC_CASE-: 8U455.E1(DOUT_2-) SITE8.E1(PAD_OUTN_TX0_CH[2])
S8_OUT_TX0_CH2_B_CASE+: 8R1106.1 8U455.B6(DIN1_2+)
S8_OUT_TX0_CH2_B_CASE-: 8R1103.1 8U455.A6(DIN1_2-)
S8_OUT_TX0_CH2_C_CASE: 8C1088.1 8R1103.2 8R1106.2
S8_OUT_TX0_CH3_ABC_CASE+: 8U456.B2(DOUT_0+) SITE8.E2(PAD_OUTP_TX0_CH[3])
S8_OUT_TX0_CH3_ABC_CASE-: 8U456.B1(DOUT_0-) SITE8.F2(PAD_OUTN_TX0_CH[3])
S8_OUT_TX0_CH3_B_CASE+: 8R1115.1 8U456.B4(DIN1_0+)
S8_OUT_TX0_CH3_B_CASE-: 8R1114.1 8U456.A4(DIN1_0-)
S8_OUT_TX0_CH3_C_CASE: 8C1093.1 8R1114.2 8R1115.2
S8_OUT_TX0_CH4_ABC_CASE+: 8U456.D2(DOUT_1+) SITE8.G1(PAD_OUTP_TX0_CH[4])
S8_OUT_TX0_CH4_ABC_CASE-: 8U456.D1(DOUT_1-) SITE8.G2(PAD_OUTN_TX0_CH[4])
S8_OUT_TX0_CH4_B_CASE+: 8R1110.1 8U456.B5(DIN1_1+)
S8_OUT_TX0_CH4_B_CASE-: 8R1111.1 8U456.A5(DIN1_1-)
S8_OUT_TX0_CH4_C_CASE: 8C1091.1 8R1110.2 8R1111.2
S8_PWR_F001: 8CA26.1 8CA27.1 8CC112.1 8SA16.1 8TP_DPS2.1(TP) SITE8.F15(DVDD_NODIE)
S8_PWR_F004: 8CA22.1 8CA23.1 8CC96.1 8SA21.1 8TP_DPS5.1(TP) SITE8.E10(AVDD33_RTC)
S8_PWR_F005: 8CA7.1 8CA8.1 8CC70.1 8CC71.1 8CC73.1 8SA8.1 8TP_DPS6.1(TP) SITE8.G18(VDDP3318_PM) SITE8.N17(VDDP3318_P0) SITE8.P3(VDDP3318_P2)
S8_PWR_F006: 8CA24.1 8CA25.1 8CC101.1 8CC103.1 8CC105.1 8SA9.1 8TP_DPS7.1(TP) SITE8.T13(VDD2_DRAM[0]) SITE8.T14(VDD2_DRAM[1]) SITE8.U13(VDD2_DRAM[2])
S8_PWR_F007: 8CA36.1 8CA37.1 8CC211.1 8CC212.1 8CC213.1 8SA23.1 8TP_DPS8.1(TP) SITE8.T10(VDDQ_DRAM[0]) SITE8.T11(VDDQ_DRAM[1]) SITE8.U11(VDDQ_DRAM[2])
S8_PWR_F008: 8CA38.1 8CA39.1 8CC220.1 8SA25.1 8TP_DPS9.1(TP) SITE8.K19(AVDD18_XTAL)
S8_PWR_GS001: 8SA15.2
S8_PWR_GS002: 8SA18.2
S8_PWR_GS003: 8SA20.2
S8_PWR_GS004: 8SA22.2
S8_PWR_GS005: 8SA7.2
S8_PWR_GS006: 8SA10.2
S8_PWR_GS007: 8SA24.2
S8_PWR_GS008: 8SA26.2
S8_PWR_M_F001: 8CA1.1 8CA2.1 8CC1.1 8CC2.1 8CC3.1 8CC4.1 8CC5.1 8CC6.1 8CC7.1 8CC8.1 8CC9.1 8CC12.1 8CC13.1 8CC14.1 8CC15.1 8CC16.1 8CC130.1 8CC214.1 8CC215.1 8CC216.1 8CC217.1 8CC218.1 8CC219.1 8K96.4 8K96.9 8SA1.1 8TP_DPS1.1(TP) SITE8.F6(AVDDL_MIPI_RX) SITE8.F7(VDD_CPU[0]) SITE8.F8(VDD_CPU[1]) SITE8.G6(AVDDL_MIPI_TX) SITE8.G7(VDD_CPU[2]) SITE8.G8(VDD_CPU[3]) SITE8.G10(VDD[0]) SITE8.G11(VDD[1]) SITE8.H7(VDD_CPU[4]) SITE8.H8(VDD_CPU[5]) SITE8.H10(VDD[2]) SITE8.H11(VDD[3]) SITE8.H12(VDD[4]) SITE8.J10(VDD[5]) SITE8.J11(VDD[6]) SITE8.J12(VDD[7]) SITE8.J13(VDD[8]) SITE8.K10(VDD[9]) SITE8.K11(VDD[10]) SITE8.K12(VDD[11]) SITE8.K13(VDD[12])
S8_PWR_M_GS001: 8SA2.2
S8_PWR_M_S001: 8SA1.2
S8_PWR_S001: 8SA16.2
S8_PWR_S002: 8SA17.2
S8_PWR_S003: 8SA19.2
S8_PWR_S004: 8SA21.2
S8_PWR_S005: 8SA8.2
S8_PWR_S006: 8SA9.2
S8_PWR_S007: 8SA23.2
S8_PWR_S008: 8SA25.2
UT1_UP5V: 7K96.1(V+) 8K96.1(V+) ; also on sheet 6 8 10 12 14 17 19 20 21 22 23 24 25 26 27 28 30 31 32 33 34 35 36 37
N22594046: 6R172.1 6U408.A1(GPU_SEL)
N22594049: 6R661.1 6U408.B7(/XSD)
N22594053: 6R662.1 6U409.A1(GPU_SEL)
N22594056: 6R663.1 6U409.B7(/XSD)
N22594080: 6R672.1 6U409.C2(DDC_AUX_SEL)
N22594118: 6R659.1 6U408.C2(DDC_AUX_SEL)
N22594226: 6R1104.1 6U455.A1(GPU_SEL)
N22594229: 6R1101.1 6U455.B7(/XSD)
N22594233: 6R1102.1 6U456.A1(GPU_SEL)
N22594236: 6R1098.1 6U456.B7(/XSD)
N22594260: 6R1108.1 6U456.C2(DDC_AUX_SEL)
N22594298: 6R1105.1 6U455.C2(DDC_AUX_SEL)
N22594406: 6BDB5.1 6R234.1
N22594408: 6BDB6.1 6R1117.1
N22594410: 6BDB8.1 6R1118.1
N22594412: 6BDB7.1 6R1119.1
N22595763: 7CA19.1 7K96.5 7K96.8
N22601908: 7R172.1 7U408.A1(GPU_SEL)
N22601911: 7R661.1 7U408.B7(/XSD)
N22601915: 7R662.1 7U409.A1(GPU_SEL)
N22601918: 7R663.1 7U409.B7(/XSD)
N22601942: 7R672.1 7U409.C2(DDC_AUX_SEL)
N22601980: 7R659.1 7U408.C2(DDC_AUX_SEL)
N22602088: 7R1104.1 7U455.A1(GPU_SEL)
N22602091: 7R1101.1 7U455.B7(/XSD)
N22602095: 7R1102.1 7U456.A1(GPU_SEL)
N22602098: 7R1098.1 7U456.B7(/XSD)
N22602122: 7R1108.1 7U456.C2(DDC_AUX_SEL)
N22602160: 7R1105.1 7U455.C2(DDC_AUX_SEL)
N22602268: 7BDB5.1 7R234.1
N22602270: 7BDB6.1 7R1117.1
N22602272: 7BDB8.1 7R1118.1
N22602274: 7BDB7.1 7R1119.1
N22603625: 8CA19.1 8K96.5 8K96.8
N22609770: 8R172.1 8U408.A1(GPU_SEL)
N22609773: 8R661.1 8U408.B7(/XSD)
N22609777: 8R662.1 8U409.A1(GPU_SEL)
N22609780: 8R663.1 8U409.B7(/XSD)
N22609804: 8R672.1 8U409.C2(DDC_AUX_SEL)
N22609842: 8R659.1 8U408.C2(DDC_AUX_SEL)
N22609950: 8R1104.1 8U455.A1(GPU_SEL)
N22609953: 8R1101.1 8U455.B7(/XSD)
N22609957: 8R1102.1 8U456.A1(GPU_SEL)
N22609960: 8R1098.1 8U456.B7(/XSD)
N22609984: 8R1108.1 8U456.C2(DDC_AUX_SEL)
N22610022: 8R1105.1 8U455.C2(DDC_AUX_SEL)
N22610130: 8BDB5.1 8R234.1
N22610132: 8BDB6.1 8R1117.1
N22610134: 8BDB8.1 8R1118.1
N22610136: 8BDB7.1 8R1119.1

Not connected (* = marked no-connect by the designer): 6U408 A8(DIN1_3+)* A9(DIN1_3-)* F1(DOUT_3-)* F2(DOUT_3+)* F8(DIN2_3+)* F9(DIN2_3-)* H1(AUX-)* H2(AUX+)* H3(HPD_2)* H5(DDC_CLK2)* H6(DAUX2+)* H8(DDC_CLK1)* H9(DAUX1+)* J1(HPDIN)* J2(HPD_1)* J3(DDC_CLK)* J5(DDC_DAT2)* J6(DAUX2-)* J7(DDC_DAT)* J8(DDC_DAT1)* J9(DAUX1-)*; 6U409 A8(DIN1_3+)* A9(DIN1_3-)* F1(DOUT_3-)* F2(DOUT_3+)* F8(DIN2_3+)* F9(DIN2_3-)* H1(AUX-)* H2(AUX+)* H3(HPD_2)* H5(DDC_CLK2)* H6(DAUX2+)* H8(DDC_CLK1)* H9(DAUX1+)* J1(HPDIN)* J2(HPD_1)* J3(DDC_CLK)* J5(DDC_DAT2)* J6(DAUX2-)* J7(DDC_DAT)* J8(DDC_DAT1)* J9(DAUX1-)*; 6U455 A8(DIN1_3+)* A9(DIN1_3-)* F1(DOUT_3-)* F2(DOUT_3+)* F8(DIN2_3+)* F9(DIN2_3-)* H1(AUX-)* H2(AUX+)* H3(HPD_2)* H5(DDC_CLK2)* H6(DAUX2+)* H8(DDC_CLK1)* H9(DAUX1+)* J1(HPDIN)* J2(HPD_1)* J3(DDC_CLK)* J5(DDC_DAT2)* J6(DAUX2-)* J7(DDC_DAT)* J8(DDC_DAT1)* J9(DAUX1-)*; 6U456 A6(DIN1_2-)* A8(DIN1_3+)* A9(DIN1_3-)* B6(DIN1_2+)* E1(DOUT_2-)* E2(DOUT_2+)* E8(DIN2_2+)* E9(DIN2_2-)* F1(DOUT_3-)* F2(DOUT_3+)* F8(DIN2_3+)* F9(DIN2_3-)* H1(AUX-)* H2(AUX+)* H3(HPD_2)* H5(DDC_CLK2)* H6(DAUX2+)* H8(DDC_CLK1)* H9(DAUX1+)* J1(HPDIN)* J2(HPD_1)* J3(DDC_CLK)* J5(DDC_DAT2)* J6(DAUX2-)* J7(DDC_DAT)* J8(DDC_DAT1)* J9(DAUX1-)*; 7K96 3* 10*; 7U408 A8(DIN1_3+)* A9(DIN1_3-)* F1(DOUT_3-)* F2(DOUT_3+)* F8(DIN2_3+)* F9(DIN2_3-)* H1(AUX-)* H2(AUX+)* H3(HPD_2)* H5(DDC_CLK2)* H6(DAUX2+)* H8(DDC_CLK1)* H9(DAUX1+)* J1(HPDIN)* J2(HPD_1)* J3(DDC_CLK)* J5(DDC_DAT2)* J6(DAUX2-)* J7(DDC_DAT)* J8(DDC_DAT1)* J9(DAUX1-)*; 7U409 A8(DIN1_3+)* A9(DIN1_3-)* F1(DOUT_3-)* F2(DOUT_3+)* F8(DIN2_3+)* F9(DIN2_3-)* H1(AUX-)* H2(AUX+)* H3(HPD_2)* H5(DDC_CLK2)* H6(DAUX2+)* H8(DDC_CLK1)* H9(DAUX1+)* J1(HPDIN)* J2(HPD_1)* J3(DDC_CLK)* J5(DDC_DAT2)* J6(DAUX2-)* J7(DDC_DAT)* J8(DDC_DAT1)* J9(DAUX1-)*; 7U455 A8(DIN1_3+)* A9(DIN1_3-)* F1(DOUT_3-)* F2(DOUT_3+)* F8(DIN2_3+)* F9(DIN2_3-)* H1(AUX-)* H2(AUX+)* H3(HPD_2)* H5(DDC_CLK2)* H6(DAUX2+)* H8(DDC_CLK1)* H9(DAUX1+)* J1(HPDIN)* J2(HPD_1)* J3(DDC_CLK)* J5(DDC_DAT2)* J6(DAUX2-)* J7(DDC_DAT)* J8(DDC_DAT1)* J9(DAUX1-)*; 7U456 A6(DIN1_2-)* A8(DIN1_3+)* A9(DIN1_3-)* B6(DIN1_2+)* E1(DOUT_2-)* E2(DOUT_2+)* E8(DIN2_2+)* E9(DIN2_2-)* F1(DOUT_3-)* F2(DOUT_3+)* F8(DIN2_3+)* F9(DIN2_3-)* H1(AUX-)* H2(AUX+)* H3(HPD_2)* H5(DDC_CLK2)* H6(DAUX2+)* H8(DDC_CLK1)* H9(DAUX1+)* J1(HPDIN)* J2(HPD_1)* J3(DDC_CLK)* J5(DDC_DAT2)* J6(DAUX2-)* J7(DDC_DAT)* J8(DDC_DAT1)* J9(DAUX1-)*; 8K96 3* 10*; 8U408 A8(DIN1_3+)* A9(DIN1_3-)* F1(DOUT_3-)* F2(DOUT_3+)* F8(DIN2_3+)* F9(DIN2_3-)* H1(AUX-)* H2(AUX+)* H3(HPD_2)* H5(DDC_CLK2)* H6(DAUX2+)* H8(DDC_CLK1)* H9(DAUX1+)* J1(HPDIN)* J2(HPD_1)* J3(DDC_CLK)* J5(DDC_DAT2)* J6(DAUX2-)* J7(DDC_DAT)* J8(DDC_DAT1)* J9(DAUX1-)*; 8U409 A8(DIN1_3+)* A9(DIN1_3-)* F1(DOUT_3-)* F2(DOUT_3+)* F8(DIN2_3+)* F9(DIN2_3-)* H1(AUX-)* H2(AUX+)* H3(HPD_2)* H5(DDC_CLK2)* H6(DAUX2+)* H8(DDC_CLK1)* H9(DAUX1+)* J1(HPDIN)* J2(HPD_1)* J3(DDC_CLK)* J5(DDC_DAT2)* J6(DAUX2-)* J7(DDC_DAT)* J8(DDC_DAT1)* J9(DAUX1-)*; 8U455 A8(DIN1_3+)* A9(DIN1_3-)* F1(DOUT_3-)* F2(DOUT_3+)* F8(DIN2_3+)* F9(DIN2_3-)* H1(AUX-)* H2(AUX+)* H3(HPD_2)* H5(DDC_CLK2)* H6(DAUX2+)* H8(DDC_CLK1)* H9(DAUX1+)* J1(HPDIN)* J2(HPD_1)* J3(DDC_CLK)* J5(DDC_DAT2)* J6(DAUX2-)* J7(DDC_DAT)* J8(DDC_DAT1)* J9(DAUX1-)*; 8U456 A6(DIN1_2-)* A8(DIN1_3+)* A9(DIN1_3-)* B6(DIN1_2+)* E1(DOUT_2-)* E2(DOUT_2+)* E8(DIN2_2+)* E9(DIN2_2-)* F1(DOUT_3-)* F2(DOUT_3+)* F8(DIN2_3+)* F9(DIN2_3-)* H1(AUX-)* H2(AUX+)* H3(HPD_2)* H5(DDC_CLK2)* H6(DAUX2+)* H8(DDC_CLK1)* H9(DAUX1+)* J1(HPDIN)* J2(HPD_1)* J3(DDC_CLK)* J5(DDC_DAT2)* J6(DAUX2-)* J7(DDC_DAT)* J8(DDC_DAT1)* J9(DAUX1-)*

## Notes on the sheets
sheet 1
- 100 ohm DIFF
- 2023.10.30
- 100 ohm DIFF
- 2023.10.30
sheet 2
- 1.53A/0.7V/0.8V
- 0.05A/0.7V/0.8V
- 0.7A/1.8V
- 0.01A/3.3V
- 200uA/3.3V
- 0.75A/3.3V/1.8V
- 0.1A/1.1V
- 0.03A/0.8V
- 0.02A/1.8V
- Trace Width: 20 mil
sheet 3
- 100 ohm DIFF
- 2023.10.30
- 100 ohm DIFF
- 2023.10.30
sheet 4
- 1.53A/0.7V/0.8V
- 0.05A/0.7V/0.8V
- 0.7A/1.8V
- 0.01A/3.3V
- 200uA/3.3V
- 0.75A/3.3V/1.8V
- 0.1A/1.1V
- 0.03A/0.8V
- 0.02A/1.8V
- Trace Width: 20 mil
sheet 5
- 100 ohm DIFF
- 2023.10.30
- 100 ohm DIFF
- 2023.10.30
